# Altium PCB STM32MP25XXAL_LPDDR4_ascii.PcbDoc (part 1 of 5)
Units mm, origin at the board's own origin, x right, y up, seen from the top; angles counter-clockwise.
Board outline 125 x 95 mm, 6 copper layers (Top Layer, Signal Layer 1, Signal Layer 2, Signal Layer 3, Signal Layer 4, Bottom Layer), stack 1.403 mm thick; 182 components, 297 nets, 1131 pads, 958 vias.
Unrouted connection lines stored in the file: 5.
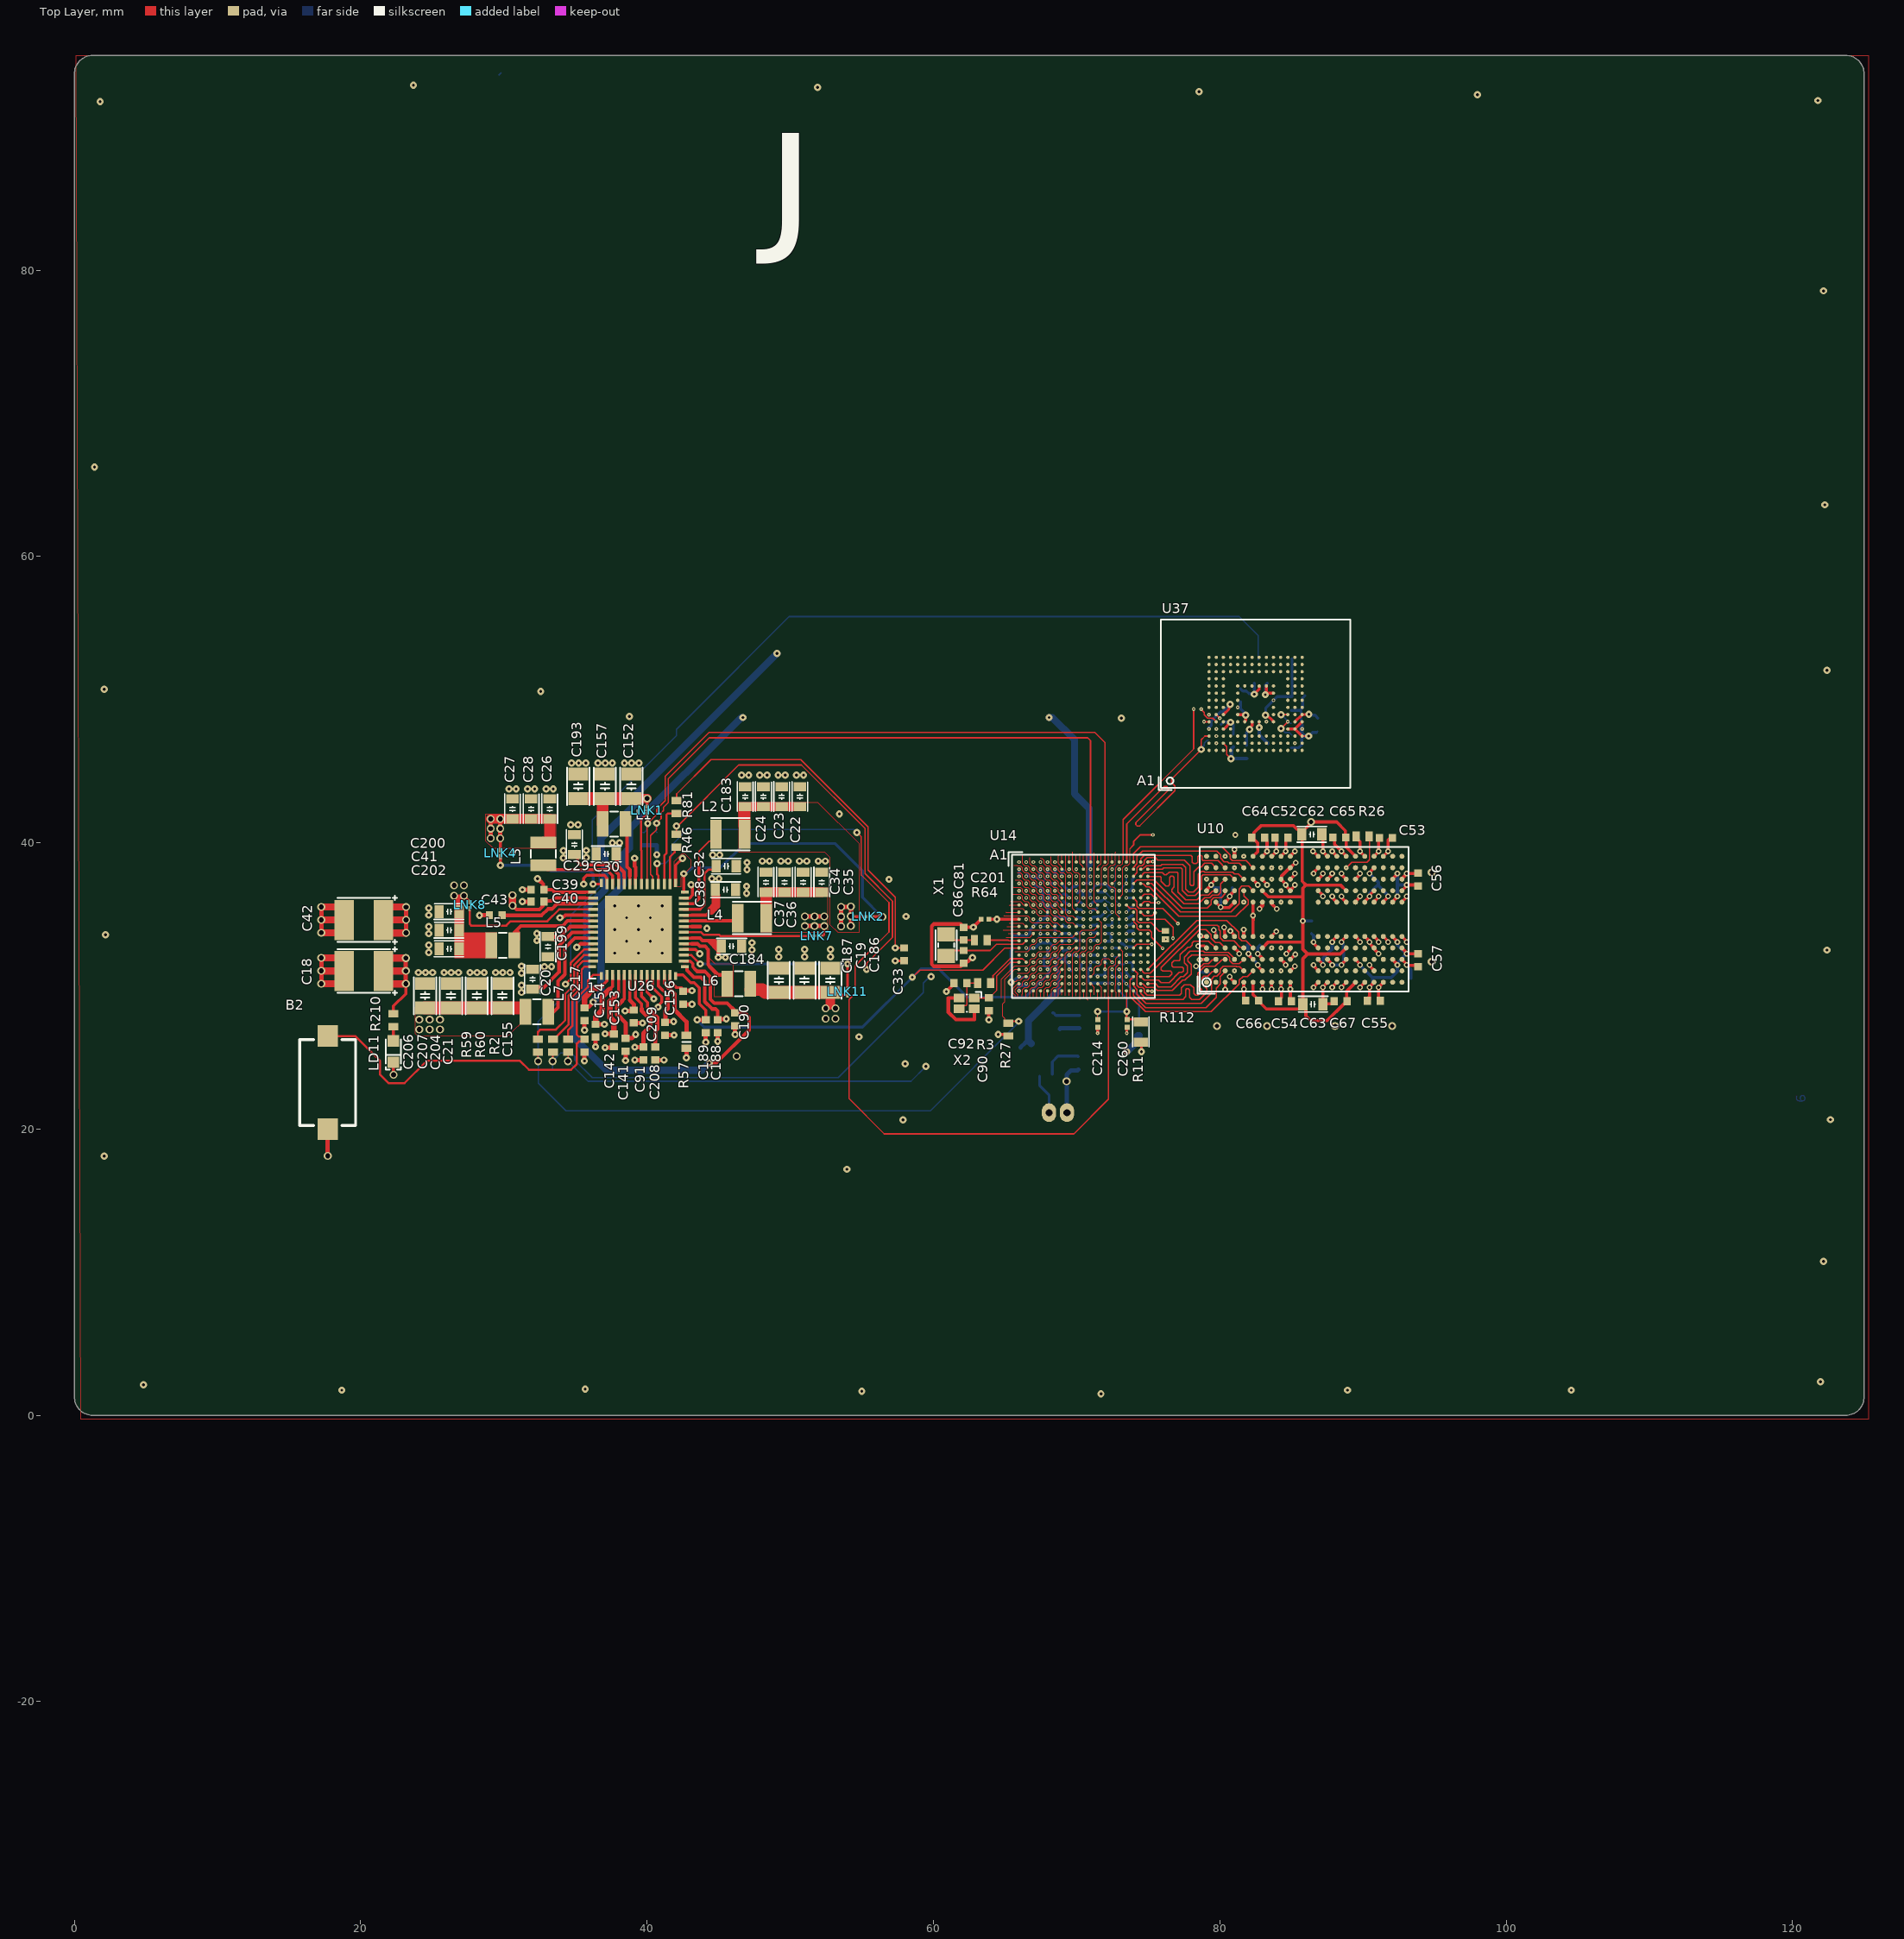
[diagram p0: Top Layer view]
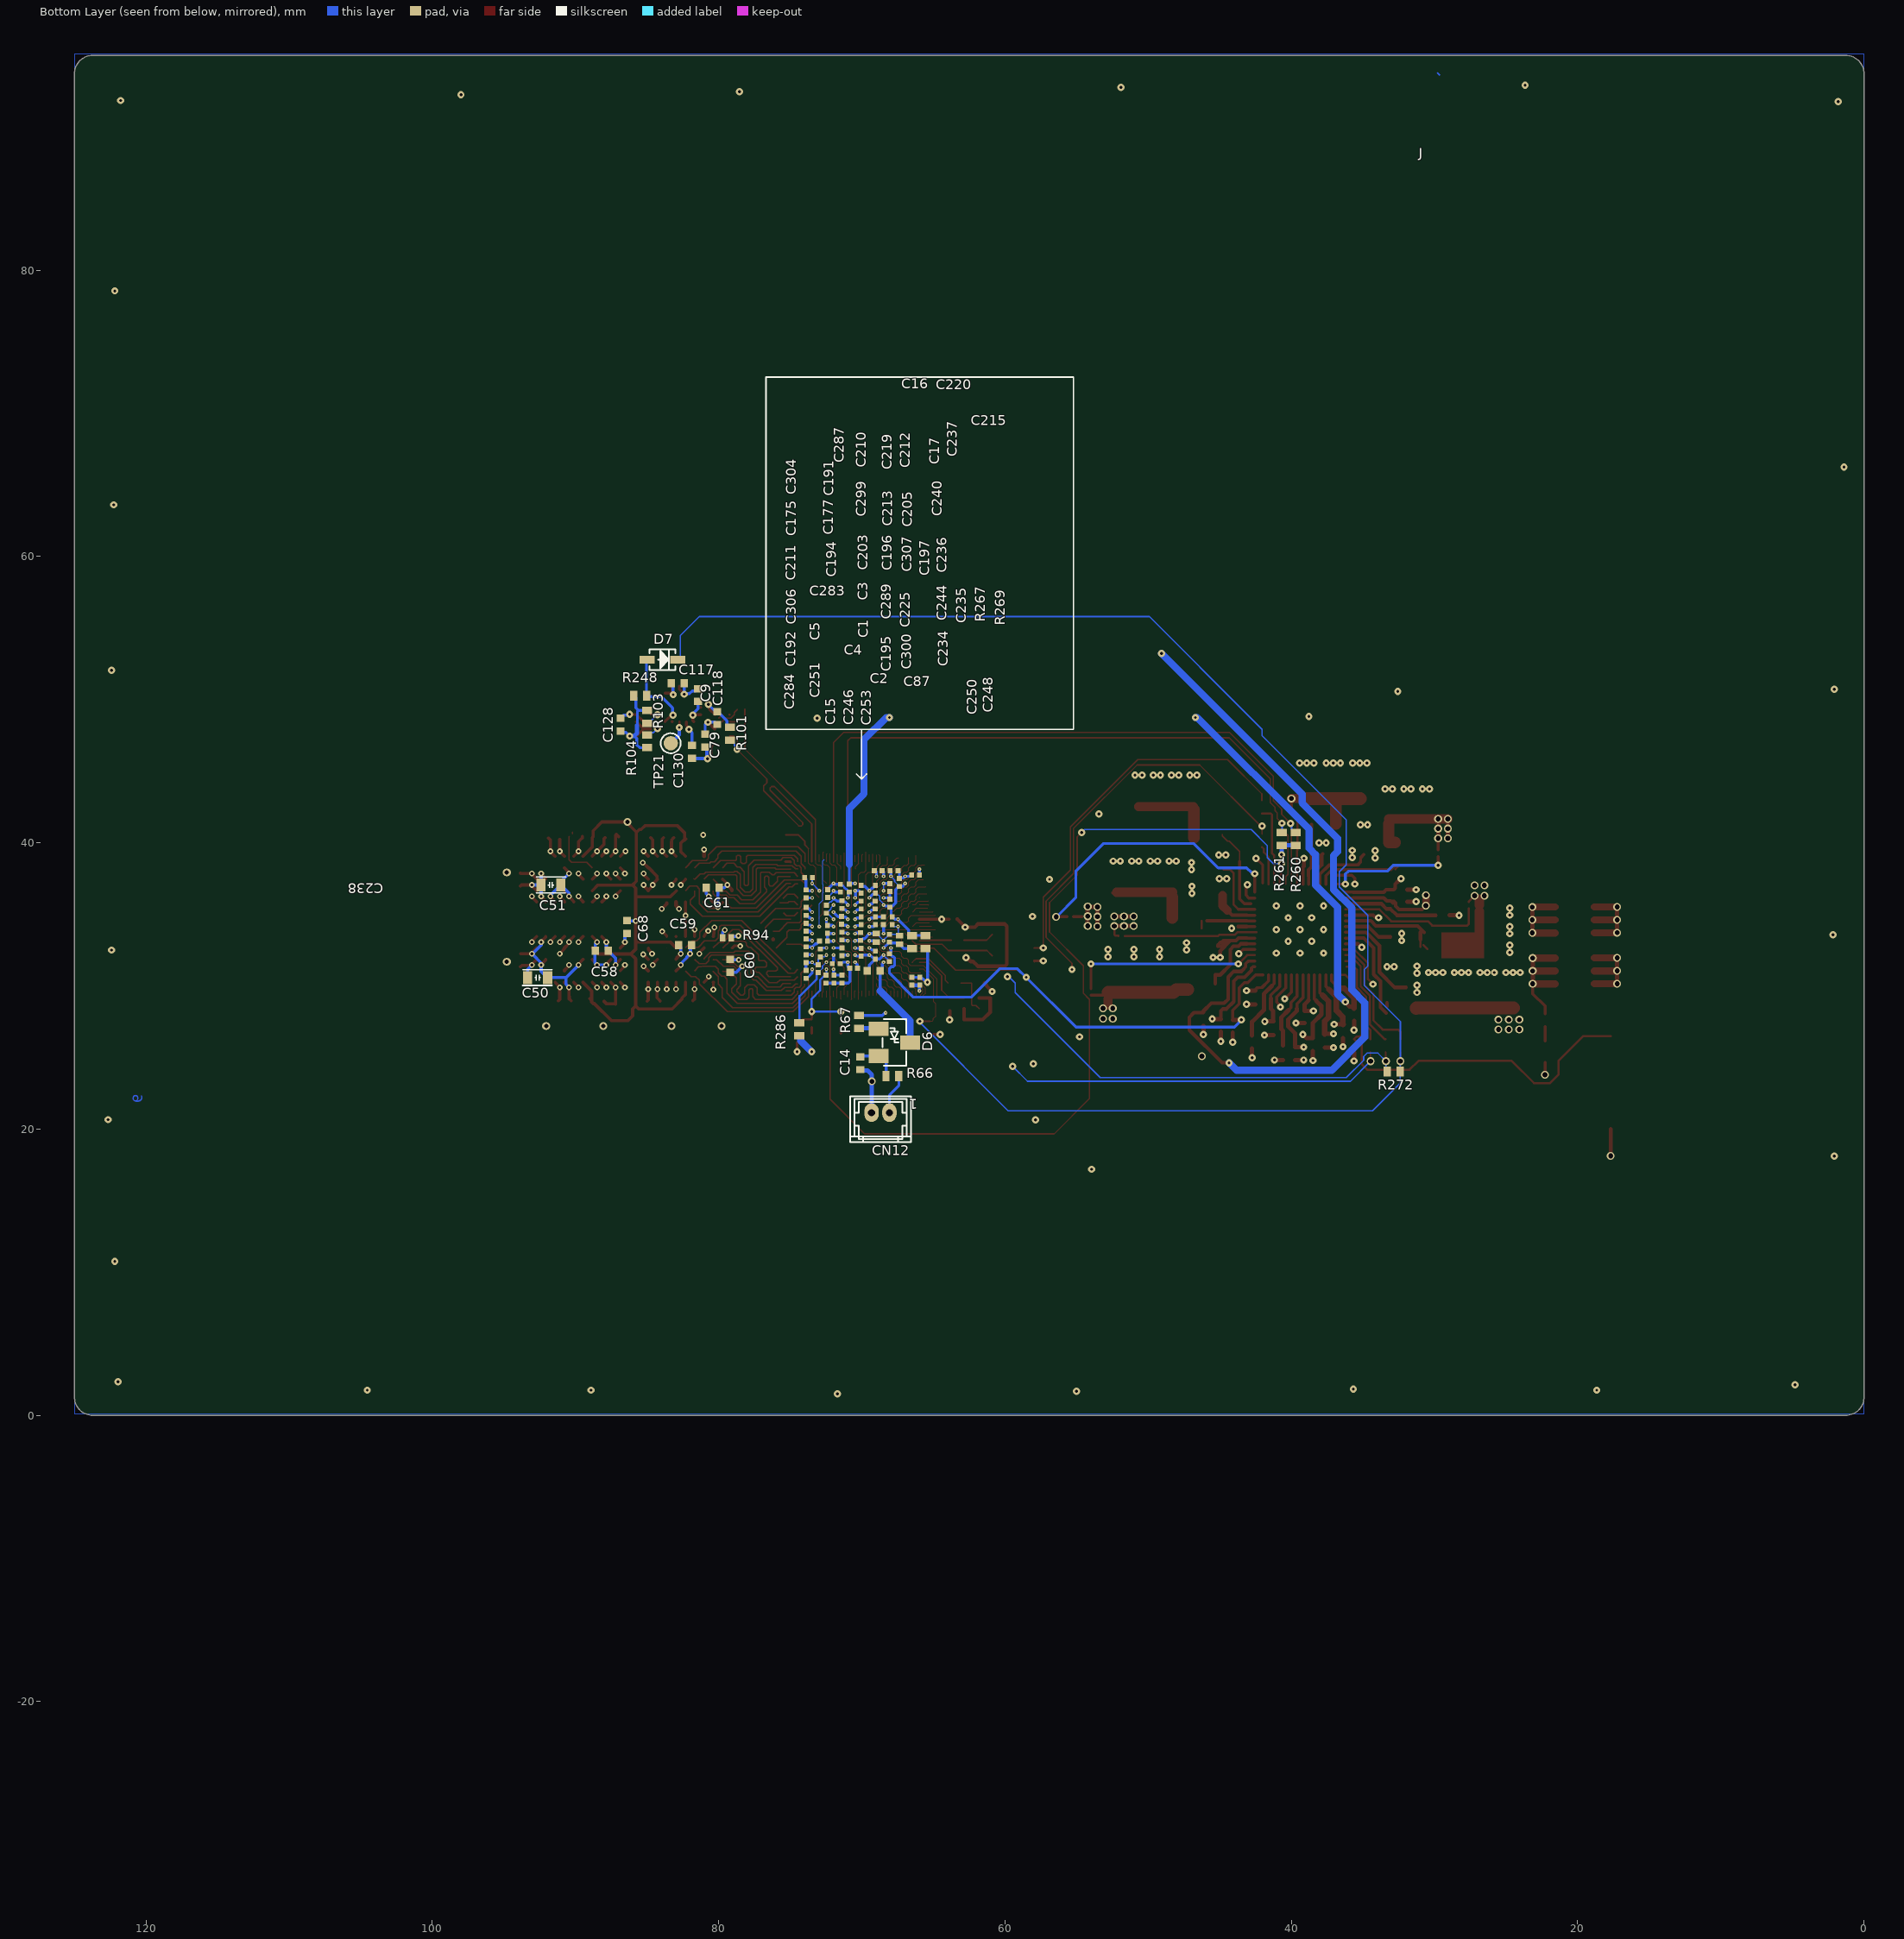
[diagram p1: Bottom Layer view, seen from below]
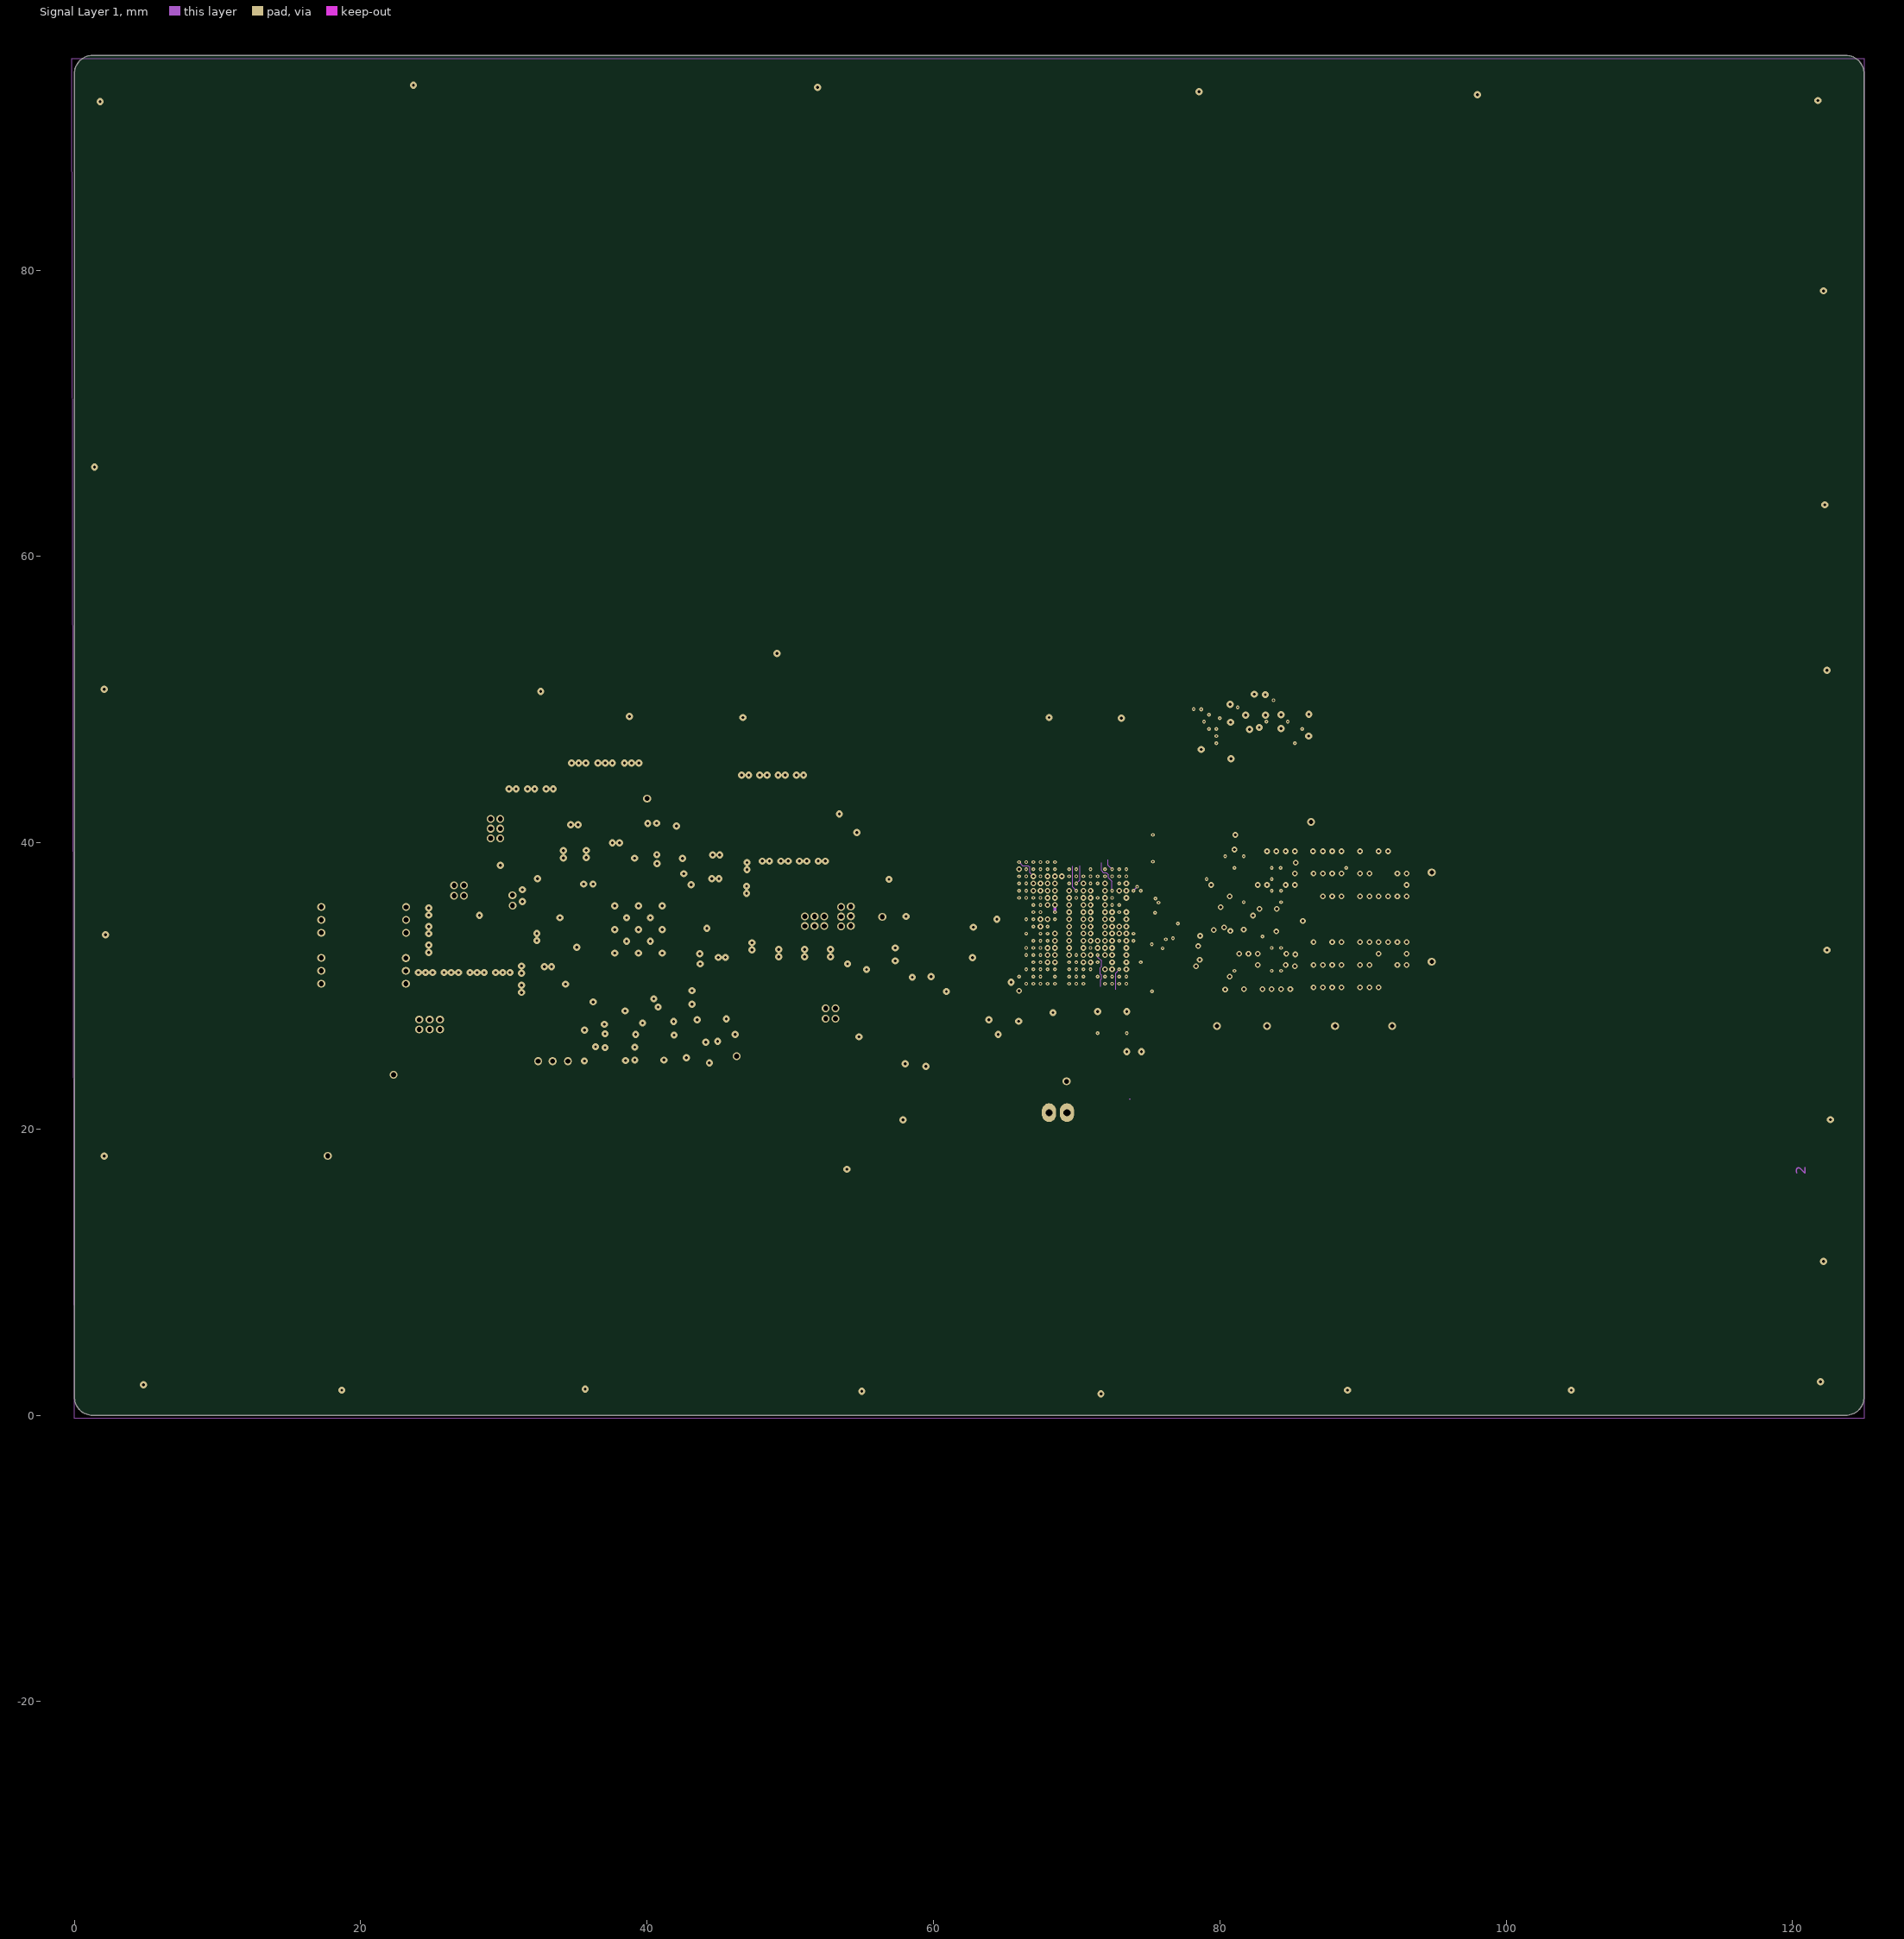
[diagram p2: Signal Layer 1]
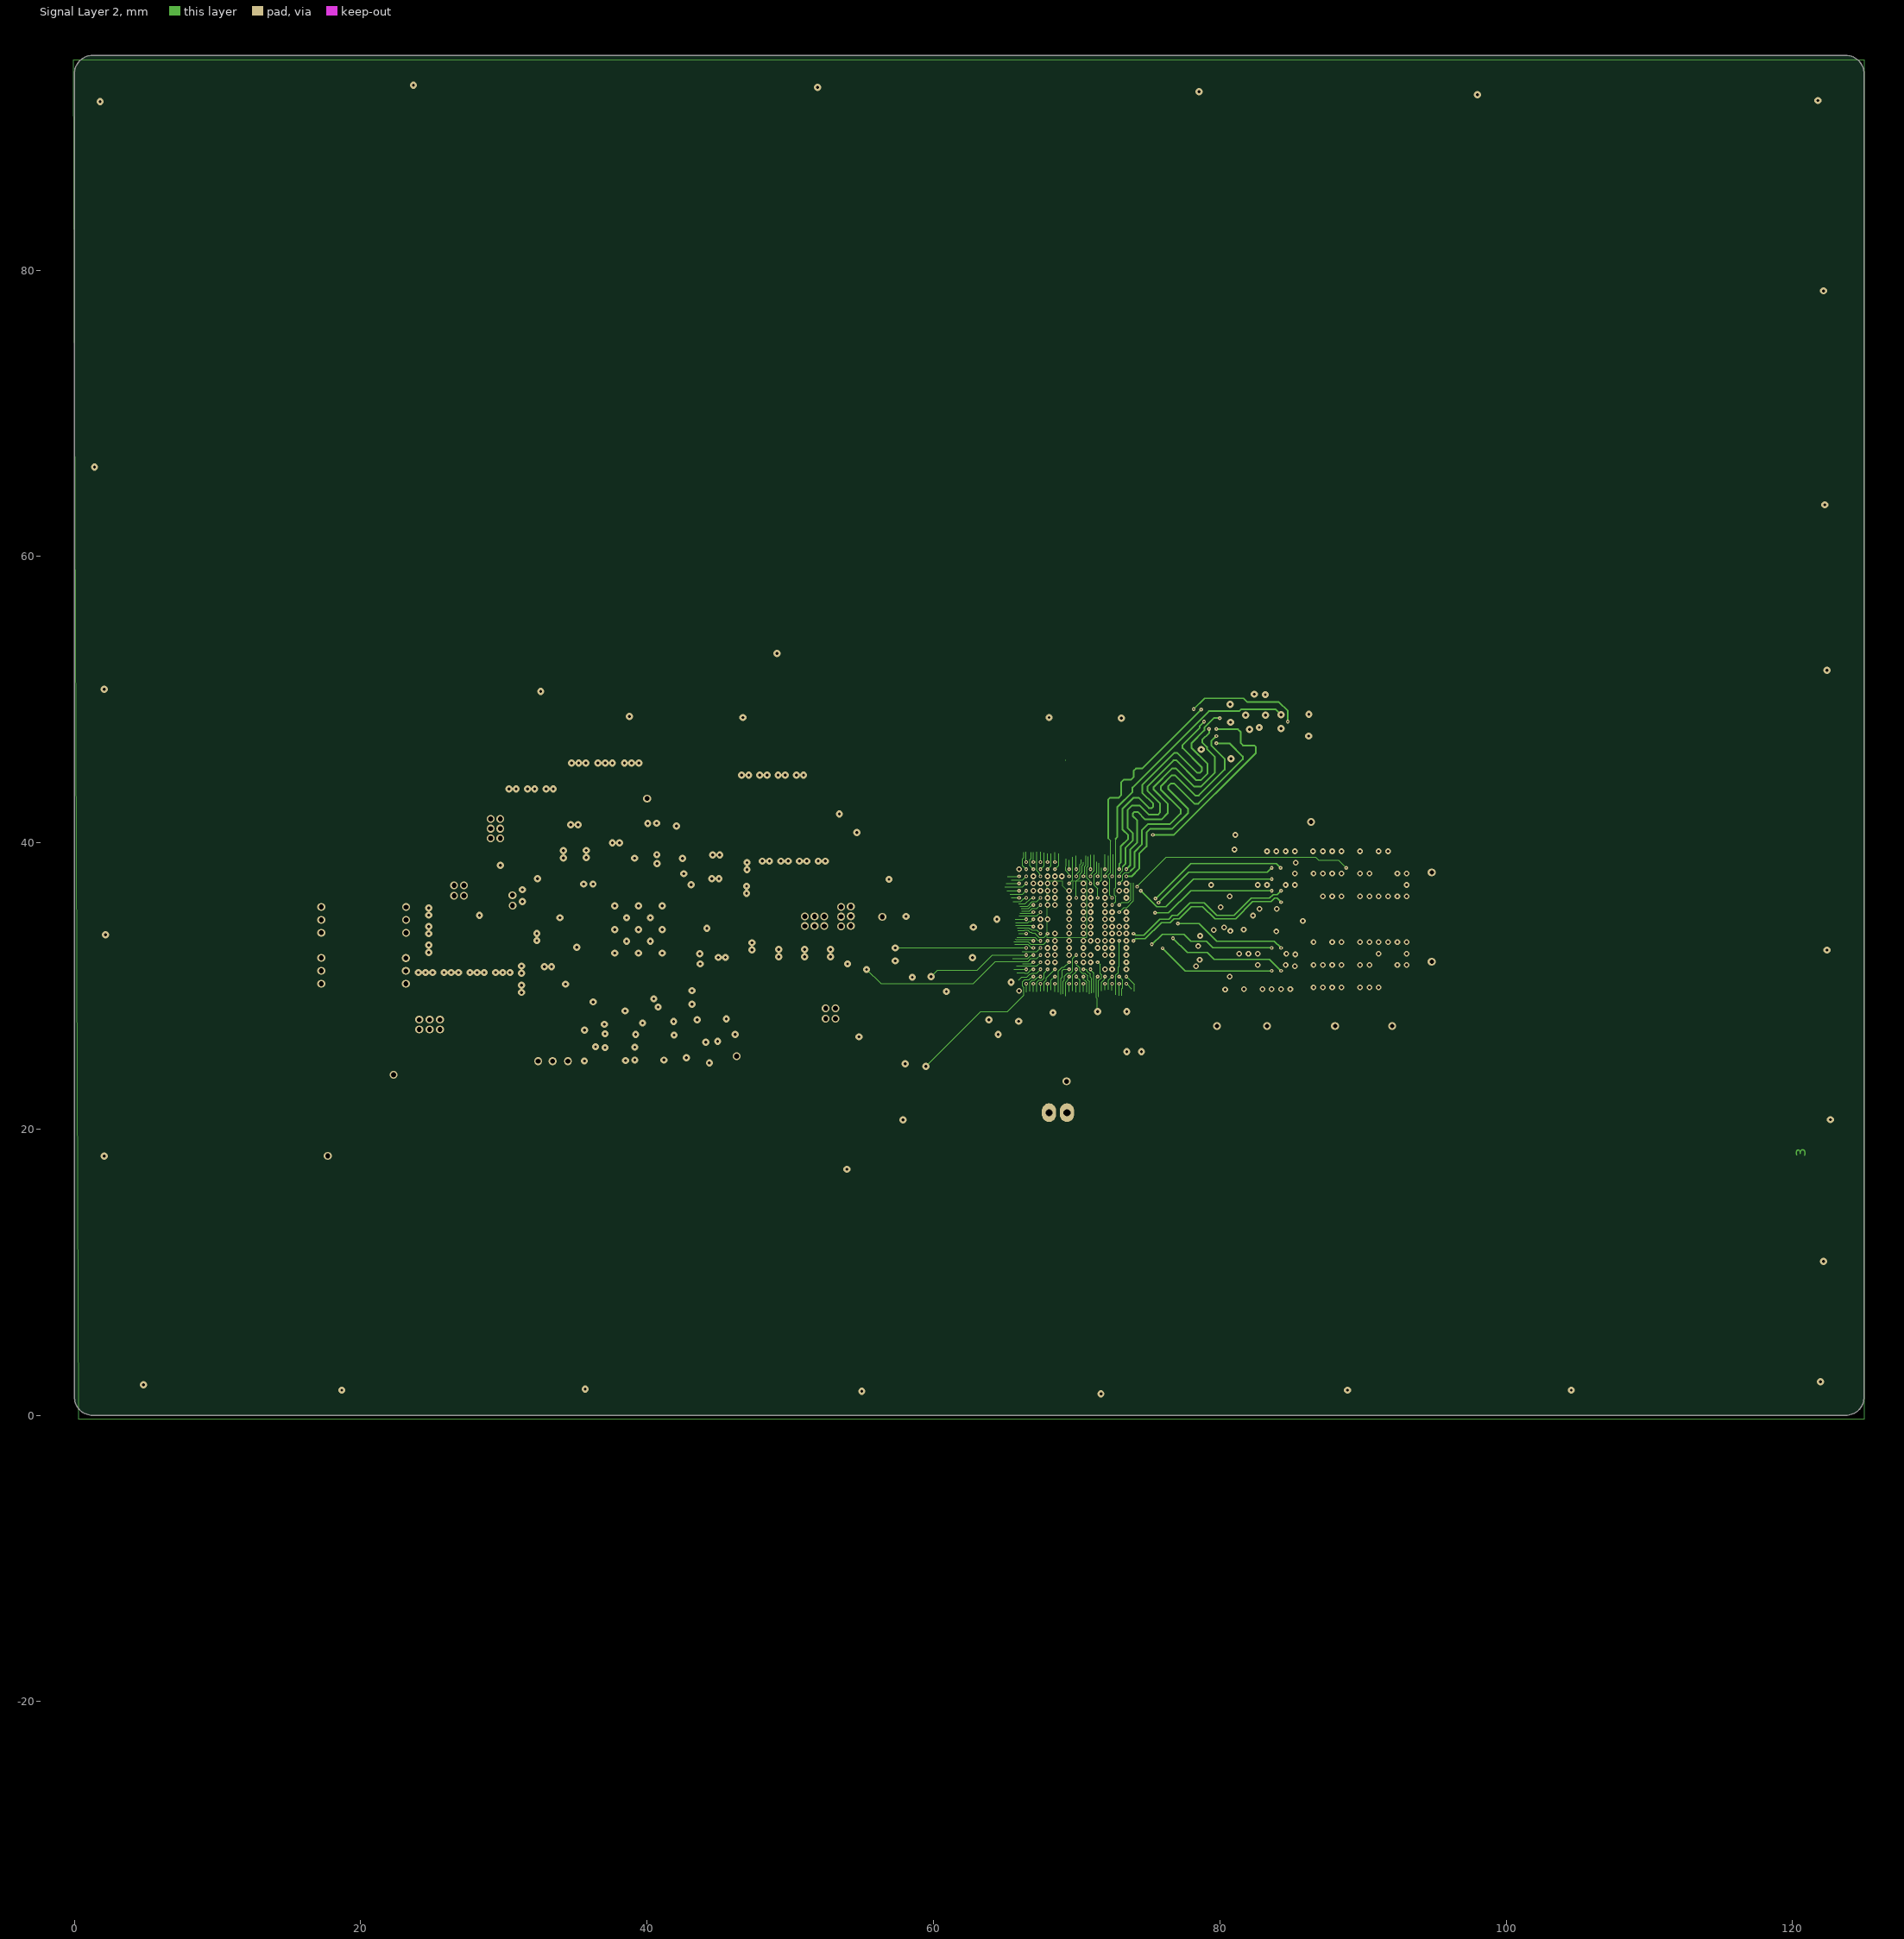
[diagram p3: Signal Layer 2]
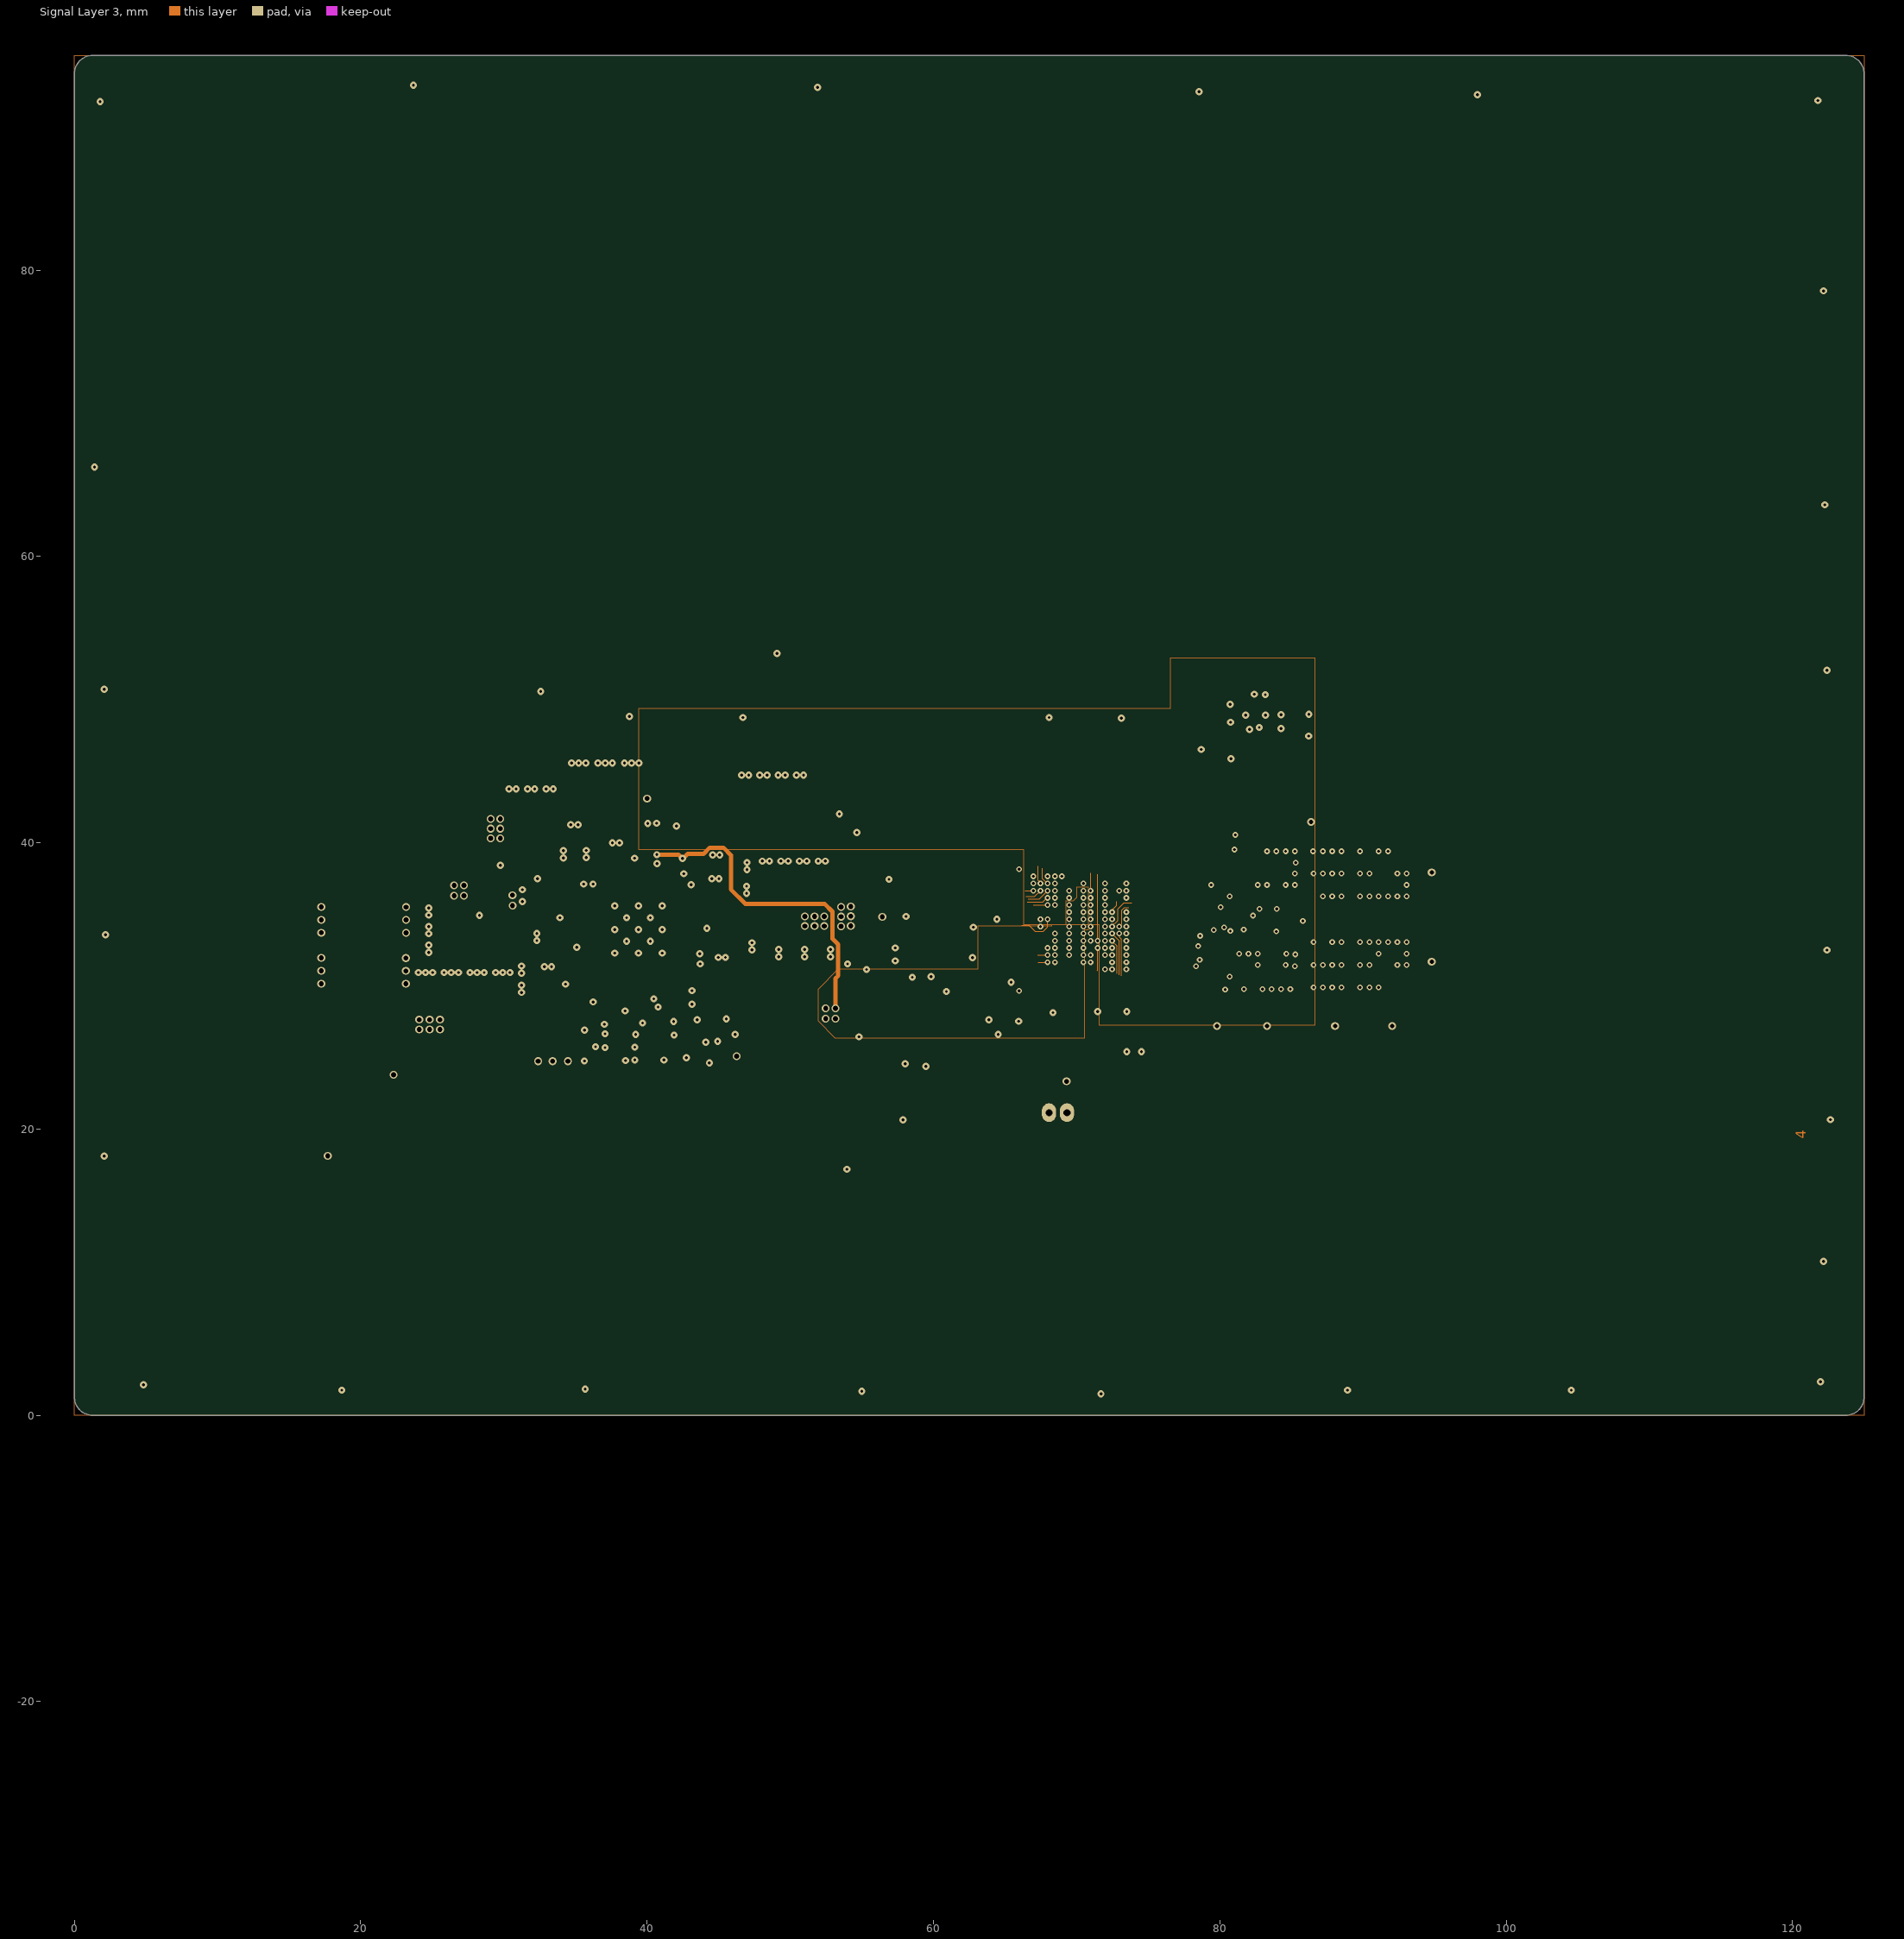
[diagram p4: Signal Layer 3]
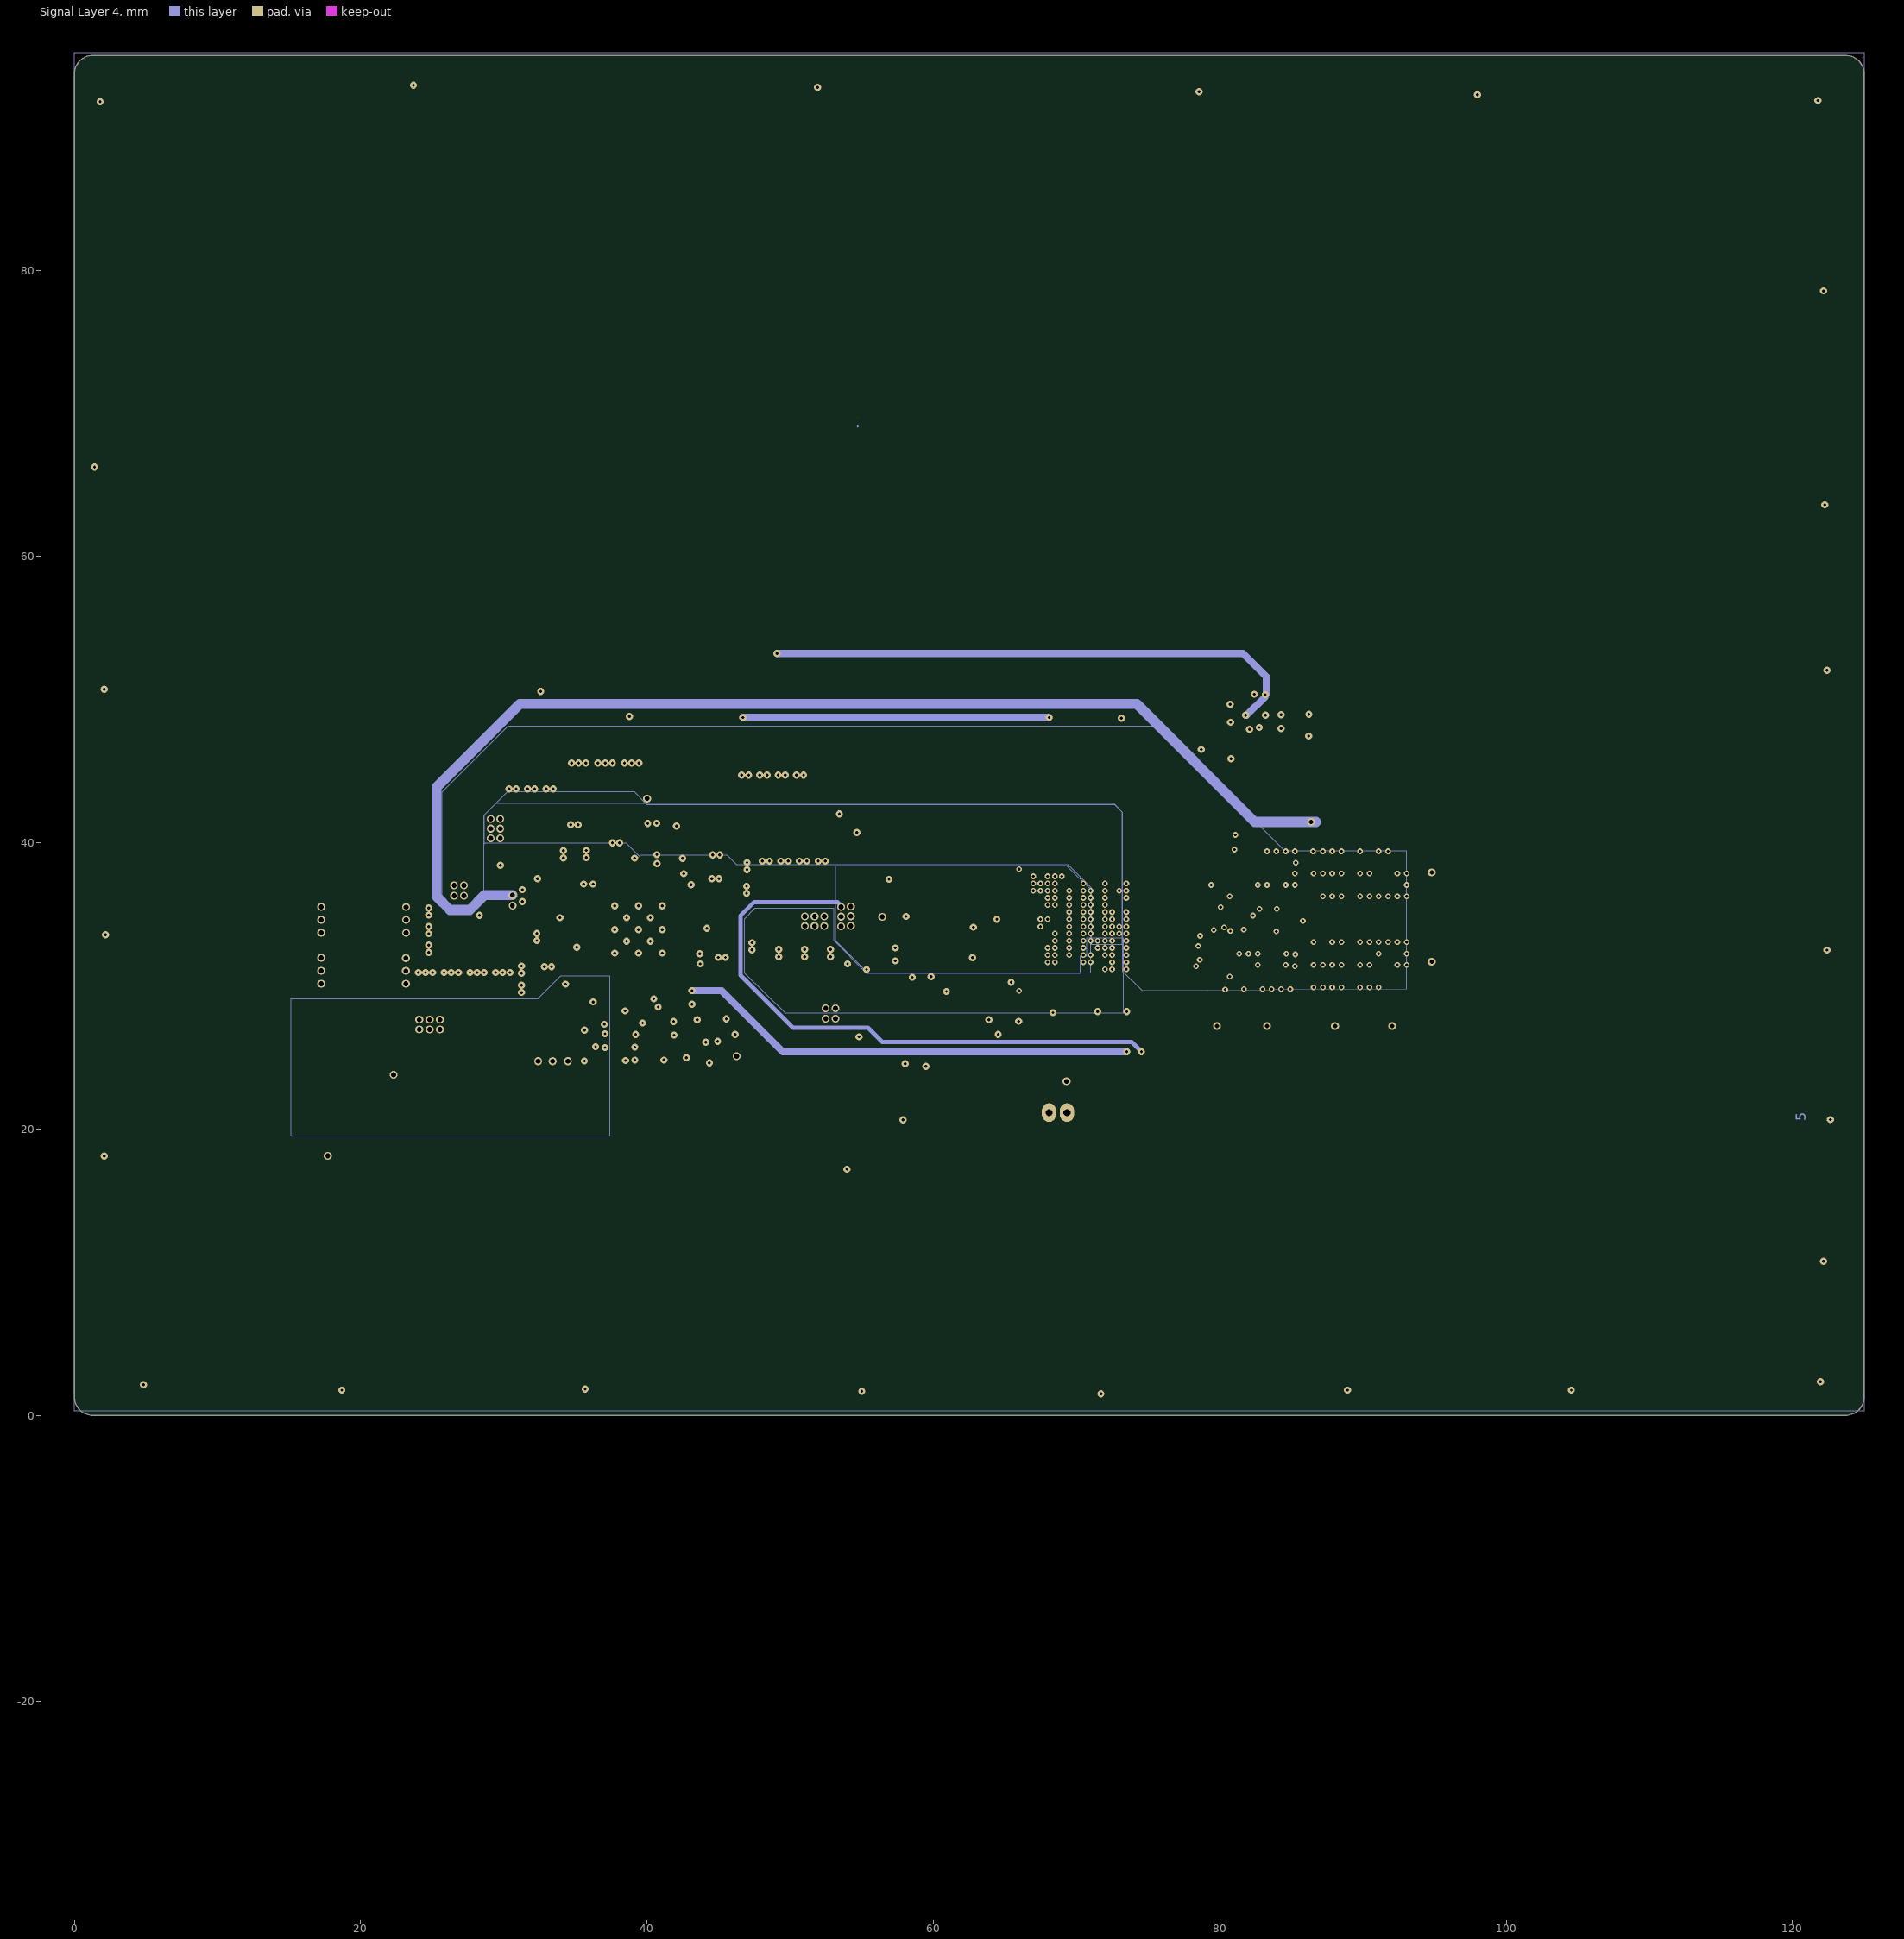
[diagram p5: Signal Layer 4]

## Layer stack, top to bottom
Top Solder: solder mask 0.025, Solder Resist, Dk 3.5
Top Layer: signal copper 0.046
Dielectric 1: prepreg 0.071, Dk 4.21
Signal Layer 1: signal copper 0.035
Dielectric 2: prepreg 0.094, Dk 4.09
Signal Layer 2: signal copper 0.023
Dielectric 3: core 0.865, Dk 4.68
Signal Layer 3: signal copper 0.023
Dielectric 4: prepreg 0.094, Dk 4.09
Signal Layer 4: signal copper 0.035
Dielectric5: prepreg 0.071, Dk 4.21
Bottom Layer: signal copper 0.046
Bottom Solder: solder mask 0.025, Solder Resist, Dk 3.5

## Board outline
0,1.27 ccw(c1.27,1.27) 1.27,0 123.73,0 ccw(c123.73,1.27) 125,1.27 125,93.73 ccw(c123.73,93.73) 123.73,95 1.27,95 ccw(c1.27,93.73) 0,93.73

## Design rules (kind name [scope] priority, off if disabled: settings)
AssemblyTestPointUsage [All] p0: scope1count=1 scope1_0_kind=Board scope1_0_value=Board scope2count=1 scope2_0_kind=Board scope2_0_value=Board commentlength=0
AssemblyTestpoint [All] p0: scope1count=1 scope1_0_kind=Board scope1_0_value=Board scope2count=1 scope2_0_kind=Board scope2_0_value=Board commentlength=0
BoardOutlineClearance [All] p0: scope1count=1 scope1_0_kind=Board scope1_0_value=Board scope2count=1 scope2_0_kind=Board scope2_0_value=Board commentlength=0 gap=0.4
BoardOutlineClearance [All] p1: gap=0.4 ignorepadtopadclearanceinfootprint=FALSE except(0: Arc-SplitContinuation Track-SplitContinuation SMDPad-SplitContinuation THPad-SplitContinuation Via-SplitContinuation Fill-SplitContinuation Poly-SplitContinuation Region-SplitContinuation Text-SplitContinuation)
Clearance [All] p0: scope1count=1 scope1_0_kind=Board scope1_0_value=Board scope2count=1 scope2_0_kind=Board scope2_0_value=Board commentlength=0 gap=0.1
Clearance [All] p1: gap=0.1 ignorepadtopadclearanceinfootprint=FALSE except(0: Arc-Hole SMDPad-Via SMDPad-Hole THPad-Hole Via-Via Via-Hole Fill-Hole Poly-Hole Region-Hole Text-Hole; 0.082: Track-Track Track-SMDPad Track-Via; 0.15: Arc-Fill Track-Fill SMDPad-Fill THPad-Fill Via-Fill Fill-Fill; 0.2: THPad-THPad)
ComponentClearance [All] p0: scope1count=1 scope1_0_kind=Footprint scope1_0_value=TP_SMD_1MM scope2count=1 scope2_0_kind=Footprint scope2_0_value="No Footprint" commentlength=0 gap=0.2 collisioncheckmode=3
ComponentClearance [HasFootprint('TP_SMD_1MM') vs HasFootprint('No Footprint')] p1: gap=0.2 collisioncheckmode=3 verticalgap=0.2 showdistances=FALSE
DiffPairsRouting [All] p0: scope1count=1 scope1_0_kind=Board scope1_0_value=Board scope2count=1 scope2_0_kind=Board scope2_0_value=Board commentlength=0
DiffPairsRouting [All] p1: maxlimit=0.16 minlimit=0.082 mostfreqgap=0.16 toplayer_mingap=0.16 toplayer_minwidth=0.075 toplayer_maxwidth=0.16 toplayer_prefwidth=0.09 midlayer1_minwidth=0.075 midlayer1_maxwidth=0.16 midlayer1_prefwidth=0.09 midlayer2_minwidth=0.075 midlayer2_maxwidth=0.16 midlayer2_prefwidth=0.09 midlayer3_minwidth=0.075 midlayer3_maxwidth=0.16 midlayer3_prefwidth=0.09 midlayer4_minwidth=0.075 midlayer4_maxwidth=0.16 midlayer4_prefwidth=0.09 bottomlayer_minwidth=0.075 bottomlayer_maxwidth=0.16 bottomlayer_prefwidth=0.09 maxuncoupledlength=12.7
FabricationTestPointUsage [All] p0: scope1count=1 scope1_0_kind=Board scope1_0_value=Board scope2count=1 scope2_0_kind=Board scope2_0_value=Board commentlength=0 valid=0 allowmultiple=FALSE
FabricationTestpoint [All] p0: scope1count=1 scope1_0_kind=Board scope1_0_value=Board scope2count=1 scope2_0_kind=Board scope2_0_value=Board commentlength=0 side=3 testpointundercomponent=TRUE minsize=1.016 maxsize=2.54 preferedsize=1.524 minholesize=0 maxholesize=1.016 preferedholesize=0.813 testpointgrid=0.025
FanoutControl Fanout_Default [All] p0: scope1count=1 scope1_0_kind=Board scope1_0_value=Board scope2count=1 scope2_0_kind=Board scope2_0_value=Board commentlength=30 // Fanout_Default (Default Rule)
FanoutControl Fanout_Small [All] p0 off: scope1count=1 scope1_0_kind=Board scope1_0_value=Board scope2count=1 scope2_0_kind=Board scope2_0_value=Board commentlength=84 // Protel DXP Scope 1 Expression Was: (CompPinCount < 5)   Fanout_Small (Default Rule)
FanoutControl Fanout_SOIC [All] p0 off: scope1count=1 scope1_0_kind=Board scope1_0_value=Board scope2count=1 scope2_0_kind=Board scope2_0_value=Board commentlength=71 // Protel DXP Scope 1 Expression Was: IsSOIC   Fanout_SOIC (Default Rule)
FanoutControl Fanout_LCC [All] p0 off: scope1count=1 scope1_0_kind=Board scope1_0_value=Board scope2count=1 scope2_0_kind=Board scope2_0_value=Board commentlength=69 // Protel DXP Scope 1 Expression Was: IsLCC   Fanout_LCC (Default Rule)
FanoutControl Fanout_BGA [All] p0 off: scope1count=1 scope1_0_kind=Board scope1_0_value=Board scope2count=1 scope2_0_kind=Board scope2_0_value=Board commentlength=69 // Protel DXP Scope 1 Expression Was: IsBGA   Fanout_BGA (Default Rule)
FanoutControl Fanout_BGA [IsBGA] p1: bgadir=Out bgaviamode=Closest fanoutstyle=Auto fanoutdirection=Alternating viagrid=0.025 // Fanout_BGA (Default Rule)
FanoutControl Fanout_LCC [IsLCC] p2: bgadir=Out bgaviamode=Closest fanoutstyle=Auto fanoutdirection=Alternating viagrid=0.025 // Fanout_LCC (Default Rule)
FanoutControl Fanout_SOIC [IsSOIC] p3: bgadir=Out bgaviamode=Closest fanoutstyle=Auto fanoutdirection=Alternating viagrid=0.025 // Fanout_SOIC (Default Rule)
FanoutControl Fanout_Small [(CompPinCount < 5)] p4: bgadir=Out bgaviamode=Closest fanoutstyle=Auto fanoutdirection=OutThenIn viagrid=0.025 // Fanout_Small (Default Rule)
FanoutControl Fanout_Default [All] p5: bgadir=Out bgaviamode=Closest fanoutstyle=Auto fanoutdirection=Alternating viagrid=0.025 // Fanout_Default (Default Rule)
Height [All] p0: scope1count=1 scope1_0_kind=Board scope1_0_value=Board scope2count=1 scope2_0_kind=Board scope2_0_value=Board commentlength=0
HoleSize [All] p0: scope1count=1 scope1_0_kind=Board scope1_0_value=Board scope2count=1 scope2_0_kind=Board scope2_0_value=Board commentlength=0 absolutevalues=TRUE maxlimit=10 minlimit=0.1 maxpercent=80.000 minpercent=20.000
HoleSize [All] p1: absolutevalues=TRUE maxlimit=10 minlimit=0.1 maxpercent=80.000 minpercent=20.000
HoleToHoleClearance [All] p0 off: scope1count=1 scope1_0_kind=Board scope1_0_value=Board scope2count=1 scope2_0_kind=Board scope2_0_value=Board commentlength=90 // Protel DXP Scope 2 Expression Was: InDrillLayerPair('Signal Layer 3 - Signal Layer 4')
HoleToHoleClearance [InDrillLayerPair('Signal Layer 3 - Signal Layer 4') vs InDrillLayerPair('Signal Layer 3 - Signal Layer 4')] p1: gap=0.26 allowstackedmicrovias=TRUE
LayerPairs [All] p0: scope1count=1 scope1_0_kind=Board scope1_0_value=Board scope2count=1 scope2_0_kind=Board scope2_0_value=Board commentlength=0 enforce=TRUE
Length Length_SDMMC1 [All] p0: scope1count=1 scope1_0_kind=NetClass scope1_0_value=SDMMC1 scope2count=1 scope2_0_kind=Board scope2_0_value=Board commentlength=0 maxlimit=100 minlimit=0
Length Length_SDMMC1 [InNetClass('SDMMC1')] p1: maxlimit=100 minlimit=0
MatchedLengths MatchedLengths_SDMMC1 [All] p0 off: scope1count=1 scope1_0_kind=Board scope1_0_value=Board scope2count=1 scope2_0_kind=Board scope2_0_value=Board commentlength=63 tolerance=5 amplitude=5.08 gap=0.508 style=90-Degree // Protel DXP Scope 1 Expression Was: InxSignalClass('SDMMC1')
MatchedLengths MatchedLengths_ETH1 [All] p0 off: scope1count=1 scope1_0_kind=Board scope1_0_value=Board scope2count=1 scope2_0_kind=Board scope2_0_value=Board commentlength=67 tolerance=10 amplitude=5.08 gap=0.508 style=90-Degree // Protel DXP Scope 1 Expression Was: InxSignalClass('RGMII_ETH1')
MatchedLengths MatchedLengths_ETH2 [All] p0 off: scope1count=1 scope1_0_kind=Board scope1_0_value=Board scope2count=1 scope2_0_kind=Board scope2_0_value=Board commentlength=67 tolerance=10 amplitude=5.08 gap=0.508 style=90-Degree // Protel DXP Scope 1 Expression Was: InxSignalClass('RGMII_ETH2')
MatchedLengths MatchedLengths_ETH1 [InxSignalClass('RGMII_ETH1')] p1: tolerance=10 checknetsindiffpair=FALSE checkdiffpairvsdiffpair=TRUE checkxsignals=TRUE checkothers=TRUE
MatchedLengths MatchedLengths_ETH2 [InxSignalClass('RGMII_ETH2')] p2: tolerance=10 checknetsindiffpair=FALSE checkdiffpairvsdiffpair=TRUE checkxsignals=TRUE checkothers=TRUE
MatchedLengths MatchedLengths_SDMMC1 [InxSignalClass('SDMMC1')] p3: tolerance=5 checknetsindiffpair=FALSE checkdiffpairvsdiffpair=TRUE checkxsignals=TRUE checkothers=TRUE
MinimumSolderMaskSliver [All] p0: scope1count=1 scope1_0_kind=Board scope1_0_value=Board scope2count=1 scope2_0_kind=Board scope2_0_value=Board commentlength=0
MinimumSolderMaskSliver [All] p1: minsoldermaskwidth=0.1
NetAntennae [All] p0: scope1count=1 scope1_0_kind=Board scope1_0_value=Board scope2count=1 scope2_0_kind=Board scope2_0_value=Board commentlength=0
PasteMaskExpansion [All] p0: scope1count=1 scope1_0_kind=Board scope1_0_value=Board scope2count=1 scope2_0_kind=Board scope2_0_value=Board commentlength=0 expansion=0
PlaneClearance [All] p0: scope1count=1 scope1_0_kind=Board scope1_0_value=Board scope2count=1 scope2_0_kind=Board scope2_0_value=Board commentlength=0 clearance=0.508
PlaneConnect [All] p0: scope1count=1 scope1_0_kind=Board scope1_0_value=Board scope2count=1 scope2_0_kind=Board scope2_0_value=Board commentlength=0 planeconnectstyle=Direct reliefexpansion=0.508 reliefentries=4 reliefconductorwidth=0.21 reliefairgap=0.21
PlaneConnect [All] p1: planeconnectstyle=Direct reliefexpansion=0.508 reliefentries=4 reliefconductorwidth=0.21 reliefairgap=0.21
PolygonConnect [All] p0: scope1count=1 scope1_0_kind=Board scope1_0_value=Board scope2count=1 scope2_0_kind=Board scope2_0_value=Board commentlength=0 connectstyle=Relief reliefconductorwidth=0.25 reliefentries=4 polygonreliefangle="90 Angle"
PolygonConnect [All] p1: thpad.connectstyle=Relief thpad.reliefconductorwidth=0.25 thpad.reliefentries=4 thpad.polygonreliefangle="90 Angle" thpad.airgapwidth=0.25 smdpad.connectstyle=NoConnect smdpad.reliefconductorwidth=0.2 smdpad.reliefentries=4 smdpad.polygonreliefangle="90 Angle" smdpad.airgapwidth=0.2 via.connectstyle=Direct via.reliefconductorwidth=0.2 via.reliefentries=4 via.polygonreliefangle="90 Angle" via.airgapwidth=0.2
RoomDefinition "U_STM32MP25XXAL Power" [All] p0: scope1count=1 scope1_0_kind=ComponentClass scope1_0_value="U_STM32MP25XXAL Power" scope2count=1 scope2_0_kind=Board scope2_0_value=Board commentlength=0 region_x1=0 region_y1=0 region_x2=20000000 region_y2=10000000 confinementstyle=ConfineIn
RoomDefinition "U_STM32MP25XXAL I_Os" [All] p0: scope1count=1 scope1_0_kind=ComponentClass scope1_0_value="U_STM32MP25XXAL I_Os" scope2count=1 scope2_0_kind=Board scope2_0_value=Board commentlength=0 region_x1=0 region_y1=0 region_x2=20000000 region_y2=10000000 confinementstyle=ConfineIn
RoomDefinition U_PMIC [All] p0: scope1count=1 scope1_0_kind=ComponentClass scope1_0_value=U_PMIC scope2count=1 scope2_0_kind=Board scope2_0_value=Board commentlength=0 region_x1=0 region_y1=0 region_x2=20000000 region_y2=10000000 confinementstyle=ConfineIn
RoomDefinition U_LPDDR4_16bits [All] p0: scope1count=1 scope1_0_kind=ComponentClass scope1_0_value=U_LPDDR4_16bits scope2count=1 scope2_0_kind=Board scope2_0_value=Board commentlength=0 region_x1=0 region_y1=0 region_x2=20000000 region_y2=10000000 confinementstyle=ConfineIn
RoomDefinition U_eMMC [All] p0: scope1count=1 scope1_0_kind=ComponentClass scope1_0_value=U_eMMC scope2count=1 scope2_0_kind=Board scope2_0_value=Board commentlength=0 region_x1=0 region_y1=0 region_x2=20000000 region_y2=10000000 confinementstyle=ConfineIn
RoomDefinition "U_STM32MP25XXAL Power" [InComponentClass('U_STM32MP25XXAL Power')] p1: confinementstyle=ConfineIn formatcopy=TRUE lockcomponents=FALSE outline -865.855,-788.22 -815.055,-788.22 -815.055,-762.82 -865.855,-762.82
RoomDefinition "U_STM32MP25XXAL I_Os" [InComponentClass('U_STM32MP25XXAL I_Os')] p2: confinementstyle=ConfineIn formatcopy=TRUE lockcomponents=FALSE outline -865.855,-788.22 -815.055,-788.22 -815.055,-762.82 -865.855,-762.82
RoomDefinition U_PMIC [InComponentClass('U_PMIC')] p3: confinementstyle=ConfineIn formatcopy=TRUE lockcomponents=FALSE outline -865.855,-788.22 -815.055,-788.22 -815.055,-762.82 -865.855,-762.82
RoomDefinition U_LPDDR4_16bits [InComponentClass('U_LPDDR4_16bits')] p4: confinementstyle=ConfineIn formatcopy=TRUE lockcomponents=FALSE outline -865.855,-788.22 -815.055,-788.22 -815.055,-762.82 -865.855,-762.82
RoomDefinition U_eMMC [InComponentClass('U_eMMC')] p5: confinementstyle=ConfineIn formatcopy=TRUE lockcomponents=FALSE outline -865.855,-788.22 -815.055,-788.22 -815.055,-762.82 -865.855,-762.82
RoutingCorners [All] p0: scope1count=1 scope1_0_kind=Board scope1_0_value=Board scope2count=1 scope2_0_kind=Board scope2_0_value=Board commentlength=0 cornerstyle=45-Degree minsetback=2.54 maxsetback=2.54
RoutingLayers [All] p0: scope1count=1 scope1_0_kind=Board scope1_0_value=Board scope2count=1 scope2_0_kind=Board scope2_0_value=Board commentlength=0 top layer=Automatic mid layer 1=Automatic mid layer 2=Automatic mid layer 3=Automatic mid layer 4=Automatic bottom layer=Automatic
RoutingPriority [All] p0: scope1count=1 scope1_0_kind=Board scope1_0_value=Board scope2count=1 scope2_0_kind=Board scope2_0_value=Board commentlength=0
RoutingTopology [All] p0: scope1count=1 scope1_0_kind=Board scope1_0_value=Board scope2count=1 scope2_0_kind=Board scope2_0_value=Board commentlength=0 topology=Shortest
RoutingVias [All] p0: scope1count=1 scope1_0_kind=Board scope1_0_value=Board scope2count=1 scope2_0_kind=Board scope2_0_value=Board commentlength=0 holewidth=0.2 width=0.4 viastyle="Through Hole" minholewidth=0.1 minwidth=0.26 maxholewidth=0.35 maxwidth=0.6
RoutingVias [All] p1: holewidth=0.2 width=0.4 viastyle="Through Hole" minholewidth=0.1 minwidth=0.26 maxholewidth=0.35 maxwidth=0.6
ShortCircuit [All] p0: scope1count=1 scope1_0_kind=Board scope1_0_value=Board scope2count=1 scope2_0_kind=Board scope2_0_value=Board commentlength=0 allowed=FALSE
SilkToBoardRegionClearance [All] p0: scope1count=1 scope1_0_kind=Board scope1_0_value=Board scope2count=1 scope2_0_kind=Board scope2_0_value=Board commentlength=0
SilkToSilkClearance [All] p0: scope1count=1 scope1_0_kind=Board scope1_0_value=Board scope2count=1 scope2_0_kind=Board scope2_0_value=Board commentlength=0
SilkToSilkClearance [All] p1: silktosilkclearance=0.2
SilkToSolderMaskClearance [All] p0 off: scope1count=1 scope1_0_kind=Board scope1_0_value=Board scope2count=1 scope2_0_kind=Board scope2_0_value=Board commentlength=44 // Protel DXP Scope 1 Expression Was: IsPad
SilkToSolderMaskClearance [IsPad] p1: minsilkscreentomaskgap=0.2 clearancetoexposedcopper=TRUE
SolderMaskExpansion [All] p0: scope1count=1 scope1_0_kind=Board scope1_0_value=Board scope2count=1 scope2_0_kind=Board scope2_0_value=Board commentlength=0 expansion=0.05
SolderMaskExpansion [All] p1: expansion=0.05 istentingtop=FALSE
UnRoutedNet [All] p0: scope1count=1 scope1_0_kind=Board scope1_0_value=Board scope2count=1 scope2_0_kind=Board scope2_0_value=Board commentlength=0
UnpouredPolygon [All] p0: scope1count=1 scope1_0_kind=Board scope1_0_value=Board scope2count=1 scope2_0_kind=Board scope2_0_value=Board commentlength=0
Width [All] p0: scope1count=1 scope1_0_kind=Board scope1_0_value=Board scope2count=1 scope2_0_kind=Board scope2_0_value=Board commentlength=0 maxlimit=10 minlimit=0.075 preferedwidth=0.1
Width [All] p1: maxlimit=10 minlimit=0.075 preferedwidth=0.1 toplayer_prefwidth=0.09 midlayer2_prefwidth=0.09 minimp=50.000000 maximp=50.000000 favimp=50.000000
17 further rules are at their usual default settings.

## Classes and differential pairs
net class eMMC.SDMMC2_D[0..7]: eMMC.SDMMC2_D0 eMMC.SDMMC2_D1 eMMC.SDMMC2_D2 eMMC.SDMMC2_D3 eMMC.SDMMC2_D4 eMMC.SDMMC2_D5 eMMC.SDMMC2_D6 eMMC.SDMMC2_D7
component class "U_STM32MP25XXAL Power": C1 C2 C3 C4 C5 C14 C15 C16 C17 C87 C175 C177 C191 C192 C194 C195 C196 C197 C201 C203 C205 C210 C211 C212 C213 C214 C215 C219 C220 C225 C234 C235 C236 C237 C238 C240 C244 C246 C248 C250 C251 C253 C260 C283 C284 C287 C289 C299 C300 C304 C306 C307 CN12 D6 R11 R66 R67 R267 R269 R286
component class "U_STM32MP25XXAL I_Os": C33 C81 C86 C90 C92 R3 R27 R64 R260 R261 R272 U14 X1 X2
component class U_PMIC: B2 C18 C19 C20 C21 C22 C23 C24 C26 C27 C28 C29 C30 C32 C34 C35 C36 C37 C38 C39 C40 C41 C42 C43 C91 C141 C142 C152 C153 C154 C155 C156 C157 C183 C184 C186 C187 C188 C189 C190 C193 C199 C200 C202 C204 C206 C207 C208 C209 C217 L1 L2 L3 L4 L5 L6 L7 LD11 LNK1 LNK2 LNK4 LNK7 LNK8 LNK11 R2 R46 R57 R59 R60 R81 R210 U26
component class U_LPDDR4_16bits: C50 C51 C52 C53 C54 C55 C56 C57 C58 C59 C60 C61 C62 C63 C64 C65 C66 C67 C68 R26 R94 R112 U10
component class U_eMMC: C9 C79 C117 C118 C128 C130 D7 R101 R103 R104 R248 TP21 U37
differential pair DDR_DQS1: +DDR_DQS1_P -DDR_DQS1_N
differential pair DDR_DQS0: +DDR_DQS0_P -DDR_DQS0_N
differential pair " ": +DDR_CLK_P -DDR_CLK_N

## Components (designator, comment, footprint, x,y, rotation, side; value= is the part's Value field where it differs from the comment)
B2 "SW_PUSH_SMD_2P" SWI_WE_434121025816 17.693,23.243 r90 top
C1 "1uF" C0201_MURATA_GRM033_H0P3 71.4,32.38 r270 bottom
C2 "1uF" C0201_MURATA_GRM033_H0P3 70.575,31.225 r180 bottom
C3 "1uF" C0201_MURATA_GRM033_H0P3 71.4,33.48 r270 bottom
C4 "1uF" C0201_MURATA_GRM033_H0P3 71.795,31.555 r0 bottom
C5 "1uF" C0201_MURATA_GRM033_H0P3 72.9,32.3 r90 bottom
C9 "Capacitor" C0402 81.451,50.313 r270 bottom
C14 "Capacitor" C0402 70.117,24.601 r90 bottom
C15 "Capacitor" C0201_MURATA_GRM033_H0P3 72.5,30.47 r90 bottom
C16 "Capacitor" C0201_MURATA_GRM033_H0P3 68.855,38.05 r180 bottom
C17 "Capacitor" C0201_MURATA_GRM033_H0P3 68.045,36.875 r90 bottom
C18 "Cap_POL_TANA" CPOL_TCJ-B_1210_H210 20.209,31.045 r180 top
C19 "Capacitor" C0805 50.998,30.389 r270 top
C20 "Capacitor" C0603 31.998,30.464 r270 top
C21 "Capacitor" C0805 29.898,29.312 r270 top
C22 "Capacitor" C0603 50.673,43.214 r270 top
C23 "Capacitor" C0603 49.398,43.214 r270 top
C24 "Capacitor" C0603 48.123,43.214 r270 top
C26 "Capacitor" C0603 33.198,42.364 r270 top
C27 "Capacitor" C0603 30.598,42.364 r270 top
C28 "Capacitor" C0603 31.898,42.364 r270 top
C29 "Capacitor" C0603 34.923,39.864 r270 top
C30 "Capacitor" C0603 37.148,39.214 r0 top
C32 "Capacitor" C0603 45.523,38.364 r180 top
C33 "Capacitor" C0402 57.955,32.2 r90 top
C34 "Capacitor" C0603 50.898,37.239 r270 top
C35 "Capacitor" C0603 52.198,37.239 r270 top
C36 "Capacitor" C0603 49.598,37.239 r270 top
C37 "Capacitor" C0603 48.298,37.239 r270 top
C38 "Capacitor" C0603 45.473,36.714 r180 top
C39 "Capacitor" C0402 32.343,36.714 r0 top
C40 "Capacitor" C0402 32.343,35.889 r0 top
C41 "Capacitor" C0603 26.173,33.889 r0 top
C42 "Cap_POL_TANA" CPOL_TCJ-B_1210_H210 20.209,34.607 r180 top
C43 "Capacitor" C0402 29.433,34.939 r0 top
C50 "Capacitor" C0603 92.65,30.575 r180 bottom
C51 "Capacitor" C0603 91.725,37.05 r0 bottom
C52 "Capacitor" C0402 84.3,40.35 r180 top
C53 "Capacitor" C0402 91.6,40.335 r0 top
C54 "Capacitor" C0402 84.55,28.935 r180 top
C55 "Capacitor" C0402 90.75,28.95 r0 top
C56 "Capacitor" C0402 93.85,37.42 r90 top
C57 "Capacitor" C0402 93.85,31.784 r270 top
C58 "Capacitor" C0402 88.175,32.45 r0 bottom
C59 "Capacitor" C0402 82.35,32.85 r0 bottom
C60 "Capacitor" C0402 79.2,31.4 r90 bottom
C61 "Capacitor" C0402 80.425,36.85 r0 bottom
C62 "Capacitor" C0603 86.425,40.585 r180 top
C63 "Capacitor" C0603 86.5,28.72 r180 top
C64 "Capacitor" C0402 82.69,40.35 r180 top
C65 "Capacitor" C0402 88.35,40.36 r0 top
C66 "Capacitor" C0402 82.25,28.97 r0 top
C67 "Capacitor" C0402 88.45,28.935 r0 top
C68 "Capacitor" C0402 86.4,34.1 r90 bottom
C79 "Capacitor" C0402 80.946,47.138 r270 bottom
C81 "Capacitor" C0402 62.112,33.645 r90 top
C86 "Capacitor" C0402 62.112,32.02 r270 top
C87 "Capacitor" C0402 69.175,31.05 r180 bottom
C90 "Capacitor" C0402 63.865,28.706 r90 top
C91 "Capacitor" C0402 39.748,25.269 r270 top
C92 "Capacitor" C0402 61.881,30.192 r180 top
C117 "Capacitor" C0402 82.861,51.148 r0 bottom
C118 "Capacitor" C0402 80.096,48.713 r90 bottom
C128 "Capacitor" C0402 86.85,48.25 r270 bottom
C130 "Capacitor" C0402 81.864,46.338 r270 bottom
C141 "Capacitor" C0402 38.498,25.889 r270 top
C142 "Capacitor" C0402 37.673,26.199 r270 top
C152 "Capacitor" C0805 38.898,43.939 r270 top
C153 "Capacitor" C0402 39.073,27.859 r90 top
C154 "Capacitor" C0402 36.398,26.864 r90 top
C155 "Capacitor" C0402 35.625,25.834 r90 top
C156 "Capacitor" C0402 42.523,29.159 r90 top
C157 "Capacitor" C0805 37.048,43.939 r270 top
C175 "Capacitor" C0201_MURATA_GRM033_H0P3 73.9,35.2 r90 bottom
C177 "Capacitor" C0201_MURATA_GRM033_H0P3 72.475,35.35 r90 bottom
C183 "Capacitor" C0603 46.848,43.214 r270 top
C184 "Capacitor" C0603 45.895,32.764 r180 top
C186 "Capacitor" C0805 52.798,30.389 r270 top
C187 "Capacitor" C0805 49.198,30.389 r270 top
C188 "Capacitor" C0402 44.923,27.179 r90 top
C189 "Capacitor" C0402 44.098,27.179 r90 top
C190 "Capacitor" C0402 46.148,27.654 r270 top
C191 "Capacitor" C0201_MURATA_GRM033_H0P3 72.38,36.45 r90 bottom
C192 "Capacitor" C0201_MURATA_GRM033_H0P3 73.9,31.9 r270 bottom
C193 "Capacitor" C0805 35.198,43.939 r270 top
C194 "Capacitor" C0201_MURATA_GRM033_H0P3 72.4,33.95 r270 bottom
C195 "Capacitor" C0201_MURATA_GRM033_H0P3 70.05,32.35 r270 bottom
C196 "Capacitor" C0201_MURATA_GRM033_H0P3 70.05,34.55 r90 bottom
C197 "Capacitor" C0201_MURATA_GRM033_H0P3 68.5,34.55 r270 bottom
C199 "Capacitor" C0603 33.073,32.739 r90 top
C200 "Capacitor" C0603 26.173,35.189 r0 top
C201 "Capacitor" C0201_MURATA_GRM033_H0P3 63.6,34.65 r0 top
C202 "Capacitor" C0603 26.173,32.589 r0 top
C203 "Capacitor" C0201_MURATA_GRM033_H0P3 71.425,34.575 r90 bottom
C204 "Capacitor" C0805 28.098,29.312 r270 top
C205 "Capacitor" C0201_MURATA_GRM033_H0P3 69.075,35.65 r270 bottom
C206 "Capacitor" C0805 24.498,29.312 r270 top
C207 "Capacitor" C0805 26.298,29.312 r270 top
C208 "Capacitor" C0402 40.573,25.269 r270 top
C209 "Capacitor" C0402 41.248,27.009 r90 top
C210 "Capacitor" C0201_MURATA_GRM033_H0P3 70.88,36.83 r90 bottom
C211 "Capacitor" C0201_MURATA_GRM033_H0P3 73.9,34.1 r90 bottom
C212 "Capacitor" C0201_MURATA_GRM033_H0P3 69.05,36.75 r270 bottom
C213 "Capacitor" C0201_MURATA_GRM033_H0P3 70.05,35.65 r90 bottom
C214 "Capacitor" C0201_MURATA_GRM033_H0P3 71.475,27.375 r90 top
C215 "Capacitor" C0201_MURATA_GRM033_H0P3 66.25,37.745 r180 bottom
C217 "Capacitor" C0402 35.623,28.009 r270 top
C219 "Capacitor" C0201_MURATA_GRM033_H0P3 70.05,36.75 r270 bottom
C220 "Capacitor" C0201_MURATA_GRM033_H0P3 67.755,38.05 r0 bottom
C225 "Capacitor" C0201_H0P5 68.995,33.35 r270 bottom
C234 "Capacitor" C0201_MURATA_GRM033_H0P3 68.07,31.97 r90 bottom
C235 "Capacitor" C0201_H0P5 67.375,33.2 r270 bottom
C236 "Capacitor" C0201_MURATA_GRM033_H0P3 67.88,34.55 r90 bottom
C237 "Capacitor" C0201_MURATA_GRM033_H0P3 67.38,37.225 r270 bottom
C238 "Capacitor" C0201_MURATA_GRM033_H0P3 73.725,37.56 r180 bottom
C240 "Capacitor" C0201_MURATA_GRM033_H0P3 68.045,35.775 r270 bottom
C244 "Capacitor" C0201_MURATA_GRM033_H0P3 68.07,33.33 r270 bottom
C246 "Capacitor" C0201_MURATA_GRM033_H0P3 71.95,30.47 r90 bottom
C248 "Capacitor" C0201_MURATA_GRM033_H0P3 65.95,30.325 r90 bottom
C250 "Capacitor" C0201_MURATA_GRM033_H0P3 66.5,30.325 r90 bottom
C251 "Capacitor" C0201_MURATA_GRM033_H0P3 73.05,31.2 r270 bottom
C253 "Capacitor" C0201_MURATA_GRM033_H0P3 71.4,30.47 r90 bottom
C260 "Capacitor" C0201_MURATA_GRM033_H0P3 73.525,27.375 r90 top
C283 "Capacitor" C0201_MURATA_GRM033_H0P3 72.675,33.125 r180 bottom
C284 "Capacitor" C0201_MURATA_GRM033_H0P3 73.9,30.8 r90 bottom
C287 "Capacitor" C0201_MURATA_GRM033_H0P3 71.5,36.825 r270 bottom
C289 "Capacitor" C0201_MURATA_GRM033_H0P3 70.1,33.45 r90 bottom
C299 "Capacitor" C0201_MURATA_GRM033_H0P3 71.4,35.68 r270 bottom
C300 "Capacitor" C0201_MURATA_GRM033_H0P3 69.05,32.15 r90 bottom
C304 "Capacitor" C0201_MURATA_GRM033_H0P3 73.9,36.425 r90 bottom
C306 "Capacitor" C0201_MURATA_GRM033_H0P3 73.9,33 r270 bottom
C307 "Capacitor" C0201_MURATA_GRM033_H0P3 69.05,34.55 r90 bottom
CN12 "Header 2x1" CON_MOLEX_53047-0210 68.699,21.141 r0 bottom
D6 "DIODE_3P_DUAL_COMMON_CATHODE" DIO_SOT23 67.726,26.042 r270 bottom
D7 "BAT60JFILM" DIO_SOD323 83.93,52.788 r180 bottom
L1 "Inductor" IND_2016_MURATA_LQM2MPN2R2NG0 37.693,41.314 r180 top
L2 "Inductor" IND_2520_TOKO_DFE252012P 45.813,40.589 r0 top
L3 "Inductor" IND_2016_MURATA_LQM2MPN2R2NG0 32.748,39.214 r90 top
L4 "Inductor" IND_2520_TOKO_DFE252012P 47.323,34.739 r0 top
L5 "Inductor" IND_2016_MURATA_LQM2MPN2R2NG0 29.923,32.839 r180 top
L6 "Inductor" IND_2016_MURATA_LQM2MPN2R2NG0 46.398,30.139 r0 top
L7 "Inductor" IND_2016_MURATA_LQM2MPN2R2NG0 32.298,28.189 r180 top
LD11 "LED_green" LED_0603_OSRAM_LG-Q396-PS-35_GREEN_1A2K_H0P4 22.284,25.411 r270 top
LNK1 "link_200" LINK200 39.998,42.262 r0 top
LNK2 "link_200" LINK200 55.439,34.839 r90 top
LNK4 "link_200" LINK200 29.748,39.264 r180 top
LNK7 "link_200" LINK200 51.848,33.489 r270 top
LNK8 "link_200" LINK200 27.598,35.637 r0 top
LNK11 "link_200" LINK200 53.998,29.579 r180 top
R2 "" R0402 34.478,25.834 r90 top
R3 "Resistor" R0402 63.531,30.192 r0 top
R11 "Resistor" R0603 74.475,26.775 r90 top
R26 "Resistor" R0402 89.975,40.435 r0 top
R27 "Resistor" R0402 65.225,26.95 r270 top
R46 "" R0402 42.048,40.137 r270 top
R57 "" R0402 42.748,26.089 r90 top
R59 "" R0402 32.378,25.834 r90 top
R60 "" R0402 33.428,25.834 r90 top
R64 "Resistor" R0402 63.312,33.195 r180 top
R66 "Resistor" R0402 67.866,23.699 r0 bottom
R67 "Resistor" R0402 70.199,27.491 r90 bottom
R81 "" R0402 42.061,42.487 r270 top
R94 "Resistor" R0201_H0P23 79.425,33.35 r0 bottom
R101 "Resistor" R0402 79.211,47.608 r90 bottom
R103 "Resistor" R0402 85.007,48.794 r90 bottom
R104 "Resistor" R0402 85.011,47.088 r270 bottom
R112 "Resistor" R0201_H0P23 76.2,33.55 r90 top
R210 "Resistor" R0402 22.284,27.604 r270 top
R248 "Resistor" R0402 85.493,50.263 r0 bottom
R260 "Resistor" R0402 39.704,40.267 r270 bottom
R261 "Resistor" R0402 40.679,40.267 r270 bottom
R267 "Resistor" R0402 66.5,33.05 r90 bottom
R269 "Resistor" R0402 65.55,33.05 r270 bottom
R272 "Resistor" R0402 32.849,24.016 r0 bottom
R286 "Resistor" R0402 74.375,26.975 r90 bottom
TP21 "Test Point" TP_SMD_1MM 83.352,46.948 r90 bottom
U10 "MT53E1G16D1ZW-046 AIT:C" ICC_TFBGA200_10X14P5_P080_H1P05 85.9,34.65 r90 top
U14 "STM32MP257FAL3" ICC_VFBGA361_10X10_P050 70.475,34.15 r0 top locked
U26 "STPMIC25APQR" ICC_QFN56-EPAD_6P5X6P5_P040 39.398,33.939 r90 top
U37 "eMMC_THGBMTG5D1LBAIL" ICC_P-WFBGA153_13X11P5_P050 82.5,49.7 r0 top locked
X1 "XTAL_2_PINS" CRY_NX2012SA_2P 60.886,32.845 r270 top
X2 "XTAL_4_PINS" CRY_NX1612SA_4P 62.331,28.781 r180 top

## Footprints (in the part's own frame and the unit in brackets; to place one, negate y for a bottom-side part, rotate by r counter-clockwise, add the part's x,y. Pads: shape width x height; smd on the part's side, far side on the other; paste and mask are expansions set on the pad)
C0201_H0P5 [mm] "MCD-01534"
  rect 0.4x0.5 smd mask+0: 1(-0.3,0) 2(0.3,0)
C0201_MURATA_GRM033_H0P3 [mm] "GRM033R60J105ME11"
  rect 0.35x0.35 smd mask+0: 1(-0.275,0) 2(0.275,0)
C0402 [mm]
  rect 0.51x0.56 smd mask+0: 1(-0.45,0) 2(0.45,0)
C0603 [mm]
  rect 0.64x0.89 smd mask+0: 1(-0.7,0) 2(0.7,0)
  silkscreen extent -1.05,-0.55 1.02,0.55
C0805 [mm]
  rect 0.9x1.4 smd mask+0: 1(-0.85,0) 2(0.85,0)
  silkscreen extent -1.3,-0.77 1.3,0.77
CON_MOLEX_53047-0210 [mm]
  oval 1x1.3 hole 0.5 mask+0: 1(-0.625,0) 2(0.625,0)
  silkscreen extent -2.12,-1.15 2.13,2.05
CPOL_TCJ-B_1210_H210 [mm] "MCD-01791"
  rect 1.35x2.8 smd mask+0: 1(-1.375,0) 2(1.375,0)
  silkscreen extent -2.33,-1.68 1.85,1.68
CRY_NX1612SA_4P [mm] "MCD-02262"
  rect 0.75x0.6 smd mask+0: 1(-0.525,-0.375) 2(0.525,-0.375) 3(0.525,0.375) 4(-0.525,0.375)
  silkscreen extent -1.02,-0.8 0.03,0.6
CRY_NX2012SA_2P [mm]
  rect 1x1.25 smd mask+0: 1(-0.75,0) 2(0.75,0)
  silkscreen extent -1.05,-0.75 1.05,0.75
DIO_SOD323 [mm]
  rect 1.06x0.54 smd mask+0: 1(-1.07,0) 2(1.07,0)
  silkscreen extent -0.9,-0.72 0.9,0.72
DIO_SOT23 [mm]
  rect 1x1.4 smd mask+0: 1(-0.95,-1.1) 2(0.95,-1.1) 3(0,1.1)
  silkscreen extent -1.63,-0.82 1.63,0.82
ICC_P-WFBGA153_13X11P5_P050 [mm]
  round 0.23 smd mask+0: A1(-3.25,-3.25) A2(-3.25,-2.75) A3(-3.25,-2.25) A4(-3.25,-1.75) A5(-3.25,-1.25) A6(-3.25,-0.75) A7(-3.25,-0.25) A8(-3.25,0.25) A9(-3.25,0.75) A10(-3.25,1.25) A11(-3.25,1.75) A12(-3.25,2.25) A13(-3.25,2.75) A14(-3.25,3.25) B1(-2.75,-3.25) B2(-2.75,-2.75) B3(-2.75,-2.25) B4(-2.75,-1.75) B5(-2.75,-1.25) B6(-2.75,-0.75) B7(-2.75,-0.25) B8(-2.75,0.25) B9(-2.75,0.75) B10(-2.75,1.25) B11(-2.75,1.75) B12(-2.75,2.25) B13(-2.75,2.75) B14(-2.75,3.25) C1(-2.25,-3.25) C2(-2.25,-2.75) C3(-2.25,-2.25) C4(-2.25,-1.75) C5(-2.25,-1.25) C6(-2.25,-0.75) C7(-2.25,-0.25) C8(-2.25,0.25) C9(-2.25,0.75) C10(-2.25,1.25) C11(-2.25,1.75) C12(-2.25,2.25) C13(-2.25,2.75) C14(-2.25,3.25) D1(-1.75,-3.25) D2(-1.75,-2.75) D3(-1.75,-2.25) D4(-1.75,-1.75) D12(-1.75,2.25) D13(-1.75,2.75) D14(-1.75,3.25) E1(-1.25,-3.25) E2(-1.25,-2.75) E3(-1.25,-2.25) E5(-1.25,-1.25) E6(-1.25,-0.75) E7(-1.25,-0.25) E8(-1.25,0.25) E9(-1.25,0.75) E10(-1.25,1.25) E12(-1.25,2.25) E13(-1.25,2.75) E14(-1.25,3.25) F1(-0.75,-3.25) F2(-0.75,-2.75) F3(-0.75,-2.25) F5(-0.75,-1.25) F10(-0.75,1.25) F12(-0.75,2.25) F13(-0.75,2.75) F14(-0.75,3.25) G1(-0.25,-3.25) G2(-0.25,-2.75) G3(-0.25,-2.25) G5(-0.25,-1.25) G10(-0.25,1.25) G12(-0.25,2.25) G13(-0.25,2.75) G14(-0.25,3.25) H1(0.25,-3.25) H2(0.25,-2.75) H3(0.25,-2.25) H5(0.25,-1.25) H10(0.25,1.25) H12(0.25,2.25) H13(0.25,2.75) H14(0.25,3.25) J1(0.75,-3.25) J2(0.75,-2.75) J3(0.75,-2.25) J5(0.75,-1.25) J10(0.75,1.25) J12(0.75,2.25) J13(0.75,2.75) J14(0.75,3.25) K1(1.25,-3.25) K2(1.25,-2.75) K3(1.25,-2.25) K5(1.25,-1.25) K6(1.25,-0.75) K7(1.25,-0.25) K8(1.25,0.25) K9(1.25,0.75) K10(1.25,1.25) K12(1.25,2.25) K13(1.25,2.75) K14(1.25,3.25) L1(1.75,-3.25) L2(1.75,-2.75) L3(1.75,-2.25) L12(1.75,2.25) L13(1.75,2.75) L14(1.75,3.25) M1(2.25,-3.25) M2(2.25,-2.75) M3(2.25,-2.25) M4(2.25,-1.75) M5(2.25,-1.25) M6(2.25,-0.75) M7(2.25,-0.25) M8(2.25,0.25) M9(2.25,0.75) M10(2.25,1.25) M11(2.25,1.75) M12(2.25,2.25) M13(2.25,2.75) M14(2.25,3.25) N1(2.75,-3.25) N2(2.75,-2.75) N3(2.75,-2.25) N4(2.75,-1.75) N5(2.75,-1.25) N6(2.75,-0.75) N7(2.75,-0.25) N8(2.75,0.25) N9(2.75,0.75) N10(2.75,1.25) N11(2.75,1.75) N12(2.75,2.25) N13(2.75,2.75) N14(2.75,3.25) P1(3.25,-3.25) P2(3.25,-2.75) P3(3.25,-2.25) P4(3.25,-1.75) P5(3.25,-1.25) P6(3.25,-0.75) P7(3.25,-0.25) P8(3.25,0.25) P9(3.25,0.75) P10(3.25,1.25) P11(3.25,1.75) P12(3.25,2.25) P13(3.25,2.75) P14(3.25,3.25)
  silkscreen extent -6.78,-6.02 6.63,5.87
ICC_QFN56-EPAD_6P5X6P5_P040 [mm] "MCD-03000"
  rect 0.55x0.21 smd mask+0: 1(-3.245,2.6) 14(-3.245,-2.6) 29(3.245,-2.6) 42(3.245,2.6)
  rect 0.7x0.21 smd mask+0: 2(-3.17,2.2) 3(-3.17,1.8) 4(-3.17,1.4) 5(-3.17,1) 6(-3.17,0.6) 7(-3.17,0.2) 8(-3.17,-0.2) 9(-3.17,-0.6) 10(-3.17,-1) 11(-3.17,-1.4) 12(-3.17,-1.8) 13(-3.17,-2.2) 30(3.17,-2.2) 31(3.17,-1.8) 32(3.17,-1.4) 33(3.17,-1) 34(3.17,-0.6) 35(3.17,-0.2) 36(3.17,0.2) 37(3.17,0.6) 38(3.17,1) 39(3.17,1.4) 40(3.17,1.8) 41(3.17,2.2)
  rect 0.21x0.55 smd mask+0: 15(-2.6,-3.245) 28(2.6,-3.245) 43(2.6,3.245) 56(-2.6,3.245)
  rect 0.21x0.7 smd mask+0: 16(-2.2,-3.17) 17(-1.8,-3.17) 18(-1.4,-3.17) 19(-1,-3.17) 20(-0.6,-3.17) 21(-0.2,-3.17) 22(0.2,-3.17) 23(0.6,-3.17) 24(1,-3.17) 25(1.4,-3.17) 26(1.8,-3.17) 27(2.2,-3.17) 44(2.2,3.17) 45(1.8,3.17) 46(1.4,3.17) 47(1,3.17) 48(0.6,3.17) 49(0.2,3.17) 50(-0.2,3.17) 51(-0.6,3.17) 52(-1,3.17) 53(-1.4,3.17) 54(-1.8,3.17) 55(-2.2,3.17)
  rect 4.7x4.7 smd mask+0: 57(0,0)
  silkscreen extent -3.44,3 -3.01,3.42
ICC_TFBGA200_10X14P5_P080_H1P05 [mm]
  round 0.35 smd mask+0: A1(-4.4,6.825) A2(-3.6,6.825) A3(-2.8,6.825) A4(-2,6.825) A5(-1.2,6.825) A8(1.2,6.825) A9(2,6.825) A10(2.8,6.825) A11(3.6,6.825) A12(4.4,6.825) AA1(-4.4,-6.175) AA2(-3.6,-6.175) AA3(-2.8,-6.175) AA4(-2,-6.175) AA5(-1.2,-6.175) AA8(1.2,-6.175) AA9(2,-6.175) AA10(2.8,-6.175) AA11(3.6,-6.175) AA12(4.4,-6.175) AB1(-4.4,-6.825) AB2(-3.6,-6.825) AB3(-2.8,-6.825) AB4(-2,-6.825) AB5(-1.2,-6.825) AB8(1.2,-6.825) AB9(2,-6.825) AB10(2.8,-6.825) AB11(3.6,-6.825) AB12(4.4,-6.825) B1(-4.4,6.175) B2(-3.6,6.175) B3(-2.8,6.175) B4(-2,6.175) B5(-1.2,6.175) B8(1.2,6.175) B9(2,6.175) B10(2.8,6.175) B11(3.6,6.175) B12(4.4,6.175) C1(-4.4,5.525) C2(-3.6,5.525) C3(-2.8,5.525) C4(-2,5.525) C5(-1.2,5.525) C8(1.2,5.525) C9(2,5.525) C10(2.8,5.525) C11(3.6,5.525) C12(4.4,5.525) D1(-4.4,4.875) D2(-3.6,4.875) D3(-2.8,4.875) D4(-2,4.875) D5(-1.2,4.875) D8(1.2,4.875) D9(2,4.875) D10(2.8,4.875) D11(3.6,4.875) D12(4.4,4.875) E1(-4.4,4.225) E2(-3.6,4.225) E3(-2.8,4.225) E4(-2,4.225) E5(-1.2,4.225) E8(1.2,4.225) E9(2,4.225) E10(2.8,4.225) E11(3.6,4.225) E12(4.4,4.225) F1(-4.4,3.575) F2(-3.6,3.575) F3(-2.8,3.575) F4(-2,3.575) F5(-1.2,3.575) F8(1.2,3.575) F9(2,3.575) F10(2.8,3.575) F11(3.6,3.575) F12(4.4,3.575) G1(-4.4,2.925) G2(-3.6,2.925) G3(-2.8,2.925) G4(-2,2.925) G5(-1.2,2.925) G8(1.2,2.925) G9(2,2.925) G10(2.8,2.925) G11(3.6,2.925) G12(4.4,2.925) H1(-4.4,2.275) H2(-3.6,2.275) H3(-2.8,2.275) H4(-2,2.275) H5(-1.2,2.275) H8(1.2,2.275) H9(2,2.275) H10(2.8,2.275) H11(3.6,2.275) H12(4.4,2.275) J1(-4.4,1.625) J2(-3.6,1.625) J3(-2.8,1.625) J4(-2,1.625) J5(-1.2,1.625) J8(1.2,1.625) J9(2,1.625) J10(2.8,1.625) J11(3.6,1.65) J12(4.4,1.625) K1(-4.4,0.975) K2(-3.6,0.975) K3(-2.8,0.975) K4(-2,0.975) K5(-1.2,0.975) K8(1.2,0.975) K9(2,0.975) K10(2.8,0.975) K11(3.6,0.975) K12(4.4,0.975) N1(-4.4,-0.975) N2(-3.6,-0.975) N3(-2.8,-0.975) N4(-2,-0.975) N5(-1.2,-0.975) N8(1.2,-0.975) N9(2,-0.975) N10(2.8,-0.975) N11(3.6,-0.975) N12(4.4,-0.975) P1(-4.4,-1.625) P2(-3.6,-1.625) P3(-2.8,-1.625) P4(-2,-1.625) P5(-1.2,-1.625) P8(1.2,-1.625) P9(2,-1.625) P10(2.8,-1.625) P11(3.6,-1.625) P12(4.4,-1.625) R1(-4.4,-2.275) R2(-3.6,-2.275) R3(-2.8,-2.275) R4(-2,-2.275) R5(-1.2,-2.275) R8(1.2,-2.275) R9(2,-2.275) R10(2.8,-2.275) R11(3.6,-2.275) R12(4.4,-2.275) T1(-4.4,-2.925) T2(-3.6,-2.925) T3(-2.8,-2.925) T4(-2,-2.925) T5(-1.2,-2.925) T8(1.2,-2.925) T9(2,-2.925) T10(2.8,-2.925) T11(3.6,-2.925) T12(4.4,-2.925) U1(-4.4,-3.575) U2(-3.6,-3.575) U3(-2.8,-3.575) U4(-2,-3.575) U5(-1.2,-3.575) U8(1.2,-3.575) U9(2,-3.575) U10(2.8,-3.575) U11(3.6,-3.575) U12(4.4,-3.575) V1(-4.4,-4.225) V2(-3.6,-4.225) V3(-2.8,-4.225) V4(-2,-4.225) V5(-1.2,-4.225) V8(1.2,-4.225) V9(2,-4.225) V10(2.8,-4.225) V11(3.6,-4.225) V12(4.4,-4.225) W1(-4.4,-4.875) W2(-3.6,-4.875) W3(-2.8,-4.875) W4(-2,-4.875) W5(-1.2,-4.875) W8(1.2,-4.875) W9(2,-4.875) W10(2.8,-4.875) W11(3.6,-4.875) W12(4.4,-4.875) Y1(-4.4,-5.525) Y2(-3.6,-5.525) Y3(-2.8,-5.525) Y4(-2,-5.525) Y5(-1.2,-5.525) Y8(1.2,-5.525) Y9(2,-5.525) Y10(2.8,-5.525) Y11(3.6,-5.525) Y12(4.4,-5.525)
  silkscreen extent -5.2,-7.3 5.05,7.45
ICC_VFBGA361_10X10_P050 [mm] "MCD-03768"
  round 0.23 smd mask+0: A1(-4.5,4.5) A2(-4,4.5) A3(-3.5,4.5) A4(-3,4.5) A5(-2.5,4.5) A6(-2,4.5) A7(-1.5,4.5) A8(-1,4.5) A9(-0.5,4.5) A10(0,4.5) A11(0.5,4.5) A12(1,4.5) A13(1.5,4.5) A14(2,4.5) A15(2.5,4.5) A16(3,4.5) A17(3.5,4.5) A18(4,4.5) A19(4.5,4.5) B1(-4.5,4) B2(-4,4) B3(-3.5,4) B4(-3,4) B5(-2.5,4) B6(-2,4) B7(-1.5,4) B8(-1,4) B9(-0.5,4) B10(0,4) B11(0.5,4) B12(1,4) B13(1.5,4) B14(2,4) B15(2.5,4) B16(3,4) B17(3.5,4) B18(4,4) B19(4.5,4) C1(-4.5,3.5) C2(-4,3.5) C3(-3.5,3.5) C4(-3,3.5) C5(-2.5,3.5) C6(-2,3.5) C7(-1.5,3.5) C8(-1,3.5) C9(-0.5,3.5) C10(0,3.5) C11(0.5,3.5) C12(1,3.5) C13(1.5,3.5) C14(2,3.5) C15(2.5,3.5) C16(3,3.5) C17(3.5,3.5) C18(4,3.5) C19(4.5,3.5) D1(-4.5,3) D2(-4,3) D3(-3.5,3) D4(-3,3) D5(-2.5,3) D6(-2,3) D7(-1.5,3) D8(-1,3) D9(-0.5,3) D10(0,3) D11(0.5,3) D12(1,3) D13(1.5,3) D14(2,3) D15(2.5,3) D16(3,3) D17(3.5,3) D18(4,3) D19(4.5,3) E1(-4.5,2.5) E2(-4,2.5) E3(-3.5,2.5) E4(-3,2.5) E5(-2.5,2.5) E6(-2,2.5) E7(-1.5,2.5) E8(-1,2.5) E9(-0.5,2.5) E10(0,2.5) E11(0.5,2.5) E12(1,2.5) E13(1.5,2.5) E14(2,2.5) E15(2.5,2.5) E16(3,2.5) E17(3.5,2.5) E18(4,2.5) E19(4.5,2.5) F1(-4.5,2) F2(-4,2) F3(-3.5,2) F4(-3,2) F5(-2.5,2) F6(-2,2) F7(-1.5,2) F8(-1,2) F9(-0.5,2) F10(0,2) F11(0.5,2) F12(1,2) F13(1.5,2) F14(2,2) F15(2.5,2) F16(3,2) F17(3.5,2) F18(4,2) F19(4.5,2) G1(-4.5,1.5) G2(-4,1.5) G3(-3.5,1.5) G4(-3,1.5) G5(-2.5,1.5) G6(-2,1.5) G7(-1.5,1.5) G8(-1,1.5) G9(-0.5,1.5) G10(0,1.5) G11(0.5,1.5) G12(1,1.5) G13(1.5,1.5) G14(2,1.5) G15(2.5,1.5) G16(3,1.5) G17(3.5,1.5) G18(4,1.5) G19(4.5,1.5) H1(-4.5,1) H2(-4,1) H3(-3.5,1) H4(-3,1) H5(-2.5,1) H6(-2,1) H7(-1.5,1) H8(-1,1) H9(-0.5,1) H10(0,1) H11(0.5,1) H12(1,1) H13(1.5,1) H14(2,1) H15(2.5,1) H16(3,1) H17(3.5,1) H18(4,1) H19(4.5,1) J1(-4.5,0.5) J2(-4,0.5) J3(-3.5,0.5) J4(-3,0.5) J5(-2.5,0.5) J6(-2,0.5) J7(-1.5,0.5) J8(-1,0.5) J9(-0.5,0.5) J10(0,0.5) J11(0.5,0.5) J12(1,0.5) J13(1.5,0.5) J14(2,0.5) J15(2.5,0.5) J16(3,0.5) J17(3.5,0.5) J18(4,0.5) J19(4.5,0.5) K1(-4.5,0) K2(-4,0) K3(-3.5,0) K4(-3,0) K5(-2.5,0) K6(-2,0) K7(-1.5,0) K8(-1,0) K9(-0.5,0) K10(0,0) K11(0.5,0) K12(1,0) K13(1.5,0) K14(2,0) K15(2.5,0) K16(3,0) K17(3.5,0) K18(4,0) K19(4.5,0) L1(-4.5,-0.5) L2(-4,-0.5) L3(-3.5,-0.5) L4(-3,-0.5) L5(-2.5,-0.5) L6(-2,-0.5) L7(-1.5,-0.5) L8(-1,-0.5) L9(-0.5,-0.5) L10(0,-0.5) L11(0.5,-0.5) L12(1,-0.5) L13(1.5,-0.5) L14(2,-0.5) L15(2.5,-0.5) L16(3,-0.5) L17(3.5,-0.5) L18(4,-0.5) L19(4.5,-0.5) M1(-4.5,-1) M2(-4,-1) M3(-3.5,-1) M4(-3,-1) M5(-2.5,-1) M6(-2,-1) M7(-1.5,-1) M8(-1,-1) M9(-0.5,-1) M10(0,-1) M11(0.5,-1) M12(1,-1) M13(1.5,-1) M14(2,-1) M15(2.5,-1) M16(3,-1) M17(3.5,-1) M18(4,-1) M19(4.5,-1) N1(-4.5,-1.5) N2(-4,-1.5) N3(-3.5,-1.5) N4(-3,-1.5) N5(-2.5,-1.5) N6(-2,-1.5) N7(-1.5,-1.5) N8(-1,-1.5) N9(-0.5,-1.5) N10(0,-1.5) N11(0.5,-1.5) N12(1,-1.5) N13(1.5,-1.5) N14(2,-1.5) N15(2.5,-1.5) N16(3,-1.5) N17(3.5,-1.5) N18(4,-1.5) N19(4.5,-1.5) P1(-4.5,-2) P2(-4,-2) P3(-3.5,-2) P4(-3,-2) P5(-2.5,-2) P6(-2,-2) P7(-1.5,-2) P8(-1,-2) P9(-0.5,-2) P10(0,-2) P11(0.5,-2) P12(1,-2) P13(1.5,-2) P14(2,-2) P15(2.5,-2) P16(3,-2) P17(3.5,-2) P18(4,-2) P19(4.5,-2) R1(-4.5,-2.5) R2(-4,-2.5) R3(-3.5,-2.5) R4(-3,-2.5) R5(-2.5,-2.5) R6(-2,-2.5) R7(-1.5,-2.5) R8(-1,-2.5) R9(-0.5,-2.5) R10(0,-2.5) R11(0.5,-2.5) R12(1,-2.5) R13(1.5,-2.5) R14(2,-2.5) R15(2.5,-2.5) R16(3,-2.5) R17(3.5,-2.5) R18(4,-2.5) R19(4.5,-2.5) T1(-4.5,-3) T2(-4,-3) T3(-3.5,-3) T4(-3,-3) T5(-2.5,-3) T6(-2,-3) T7(-1.5,-3) T8(-1,-3) T9(-0.5,-3) T10(0,-3) T11(0.5,-3) T12(1,-3) T13(1.5,-3) T14(2,-3) T15(2.5,-3) T16(3,-3) T17(3.5,-3) T18(4,-3) T19(4.5,-3) U1(-4.5,-3.5) U2(-4,-3.5) U3(-3.5,-3.5) U4(-3,-3.5) U5(-2.5,-3.5) U6(-2,-3.5) U7(-1.5,-3.5) U8(-1,-3.5) U9(-0.5,-3.5) U10(0,-3.5) U11(0.5,-3.5) U12(1,-3.5) U13(1.5,-3.5) U14(2,-3.5) U15(2.5,-3.5) U16(3,-3.5) U17(3.5,-3.5) U18(4,-3.5) U19(4.5,-3.5) V1(-4.5,-4) V2(-4,-4) V3(-3.5,-4) V4(-3,-4) V5(-2.5,-4) V6(-2,-4) V7(-1.5,-4) V8(-1,-4) V9(-0.5,-4) V10(0,-4) V11(0.5,-4) V12(1,-4) V13(1.5,-4) V14(2,-4) V15(2.5,-4) V16(3,-4) V17(3.5,-4) V18(4,-4) V19(4.5,-4) W1(-4.5,-4.5) W2(-4,-4.5) W3(-3.5,-4.5) W4(-3,-4.5) W5(-2.5,-4.5) W6(-2,-4.5) W7(-1.5,-4.5) W8(-1,-4.5) W9(-0.5,-4.5) W10(0,-4.5) W11(0.5,-4.5) W12(1,-4.5) W13(1.5,-4.5) W14(2,-4.5) W15(2.5,-4.5) W16(3,-4.5) W17(3.5,-4.5) W18(4,-4.5) W19(4.5,-4.5)
  silkscreen extent -5.25,-5 5,5.2
IND_2016_MURATA_LQM2MPN2R2NG0 [mm] "MCD-03141"
  rect 0.8x1.8 smd mask+0: 1(-0.8,0) 2(0.8,0)
  silkscreen extent -0.28,-0.87 0.28,0.87
IND_2520_TOKO_DFE252012P [mm] "MCD-02254"
  rect 0.8x2 smd mask+0: 1(-1,0) 2(1,0)
  silkscreen extent -1.35,-1.12 1.35,1.12
LED_0603_OSRAM_LG-Q396-PS-35_GREEN_1A2K_H0P4 [mm]
  rect 0.8x0.8 smd mask+0: 1(-0.75,0) 2(0.75,0)
  silkscreen extent -0.85,-0.53 1.28,0.53
LINK200 [mm]
  rect 0.2x0.35 smd paste-10 mask+0: 1(0,-0.225) 2(0,0.225)
R0201_H0P23 [mm]
  rect 0.4x0.5 smd mask+0: 1(-0.3,0) 2(0.3,0)
R0402 [mm]
  rect 0.51x0.7 smd mask+0: 1(-0.45,0) 2(0.45,0)
R0603 [mm]
  rect 0.64x1 smd mask+0: 1(-0.7,0) 2(0.7,0)
  silkscreen extent -1.05,-0.58 1.05,0.58
SWI_WE_434121025816 [mm] "MCD-03492"
  rect 1.5x1.4 smd: 1(-3.25,0) 2(3.25,0)
  silkscreen extent -3,-1.95 3,1.95
TP_SMD_1MM [mm]
  round 1 smd paste-10 mask+0: 1(0,0)
  silkscreen extent -0.7,-0.7 0.7,0.7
